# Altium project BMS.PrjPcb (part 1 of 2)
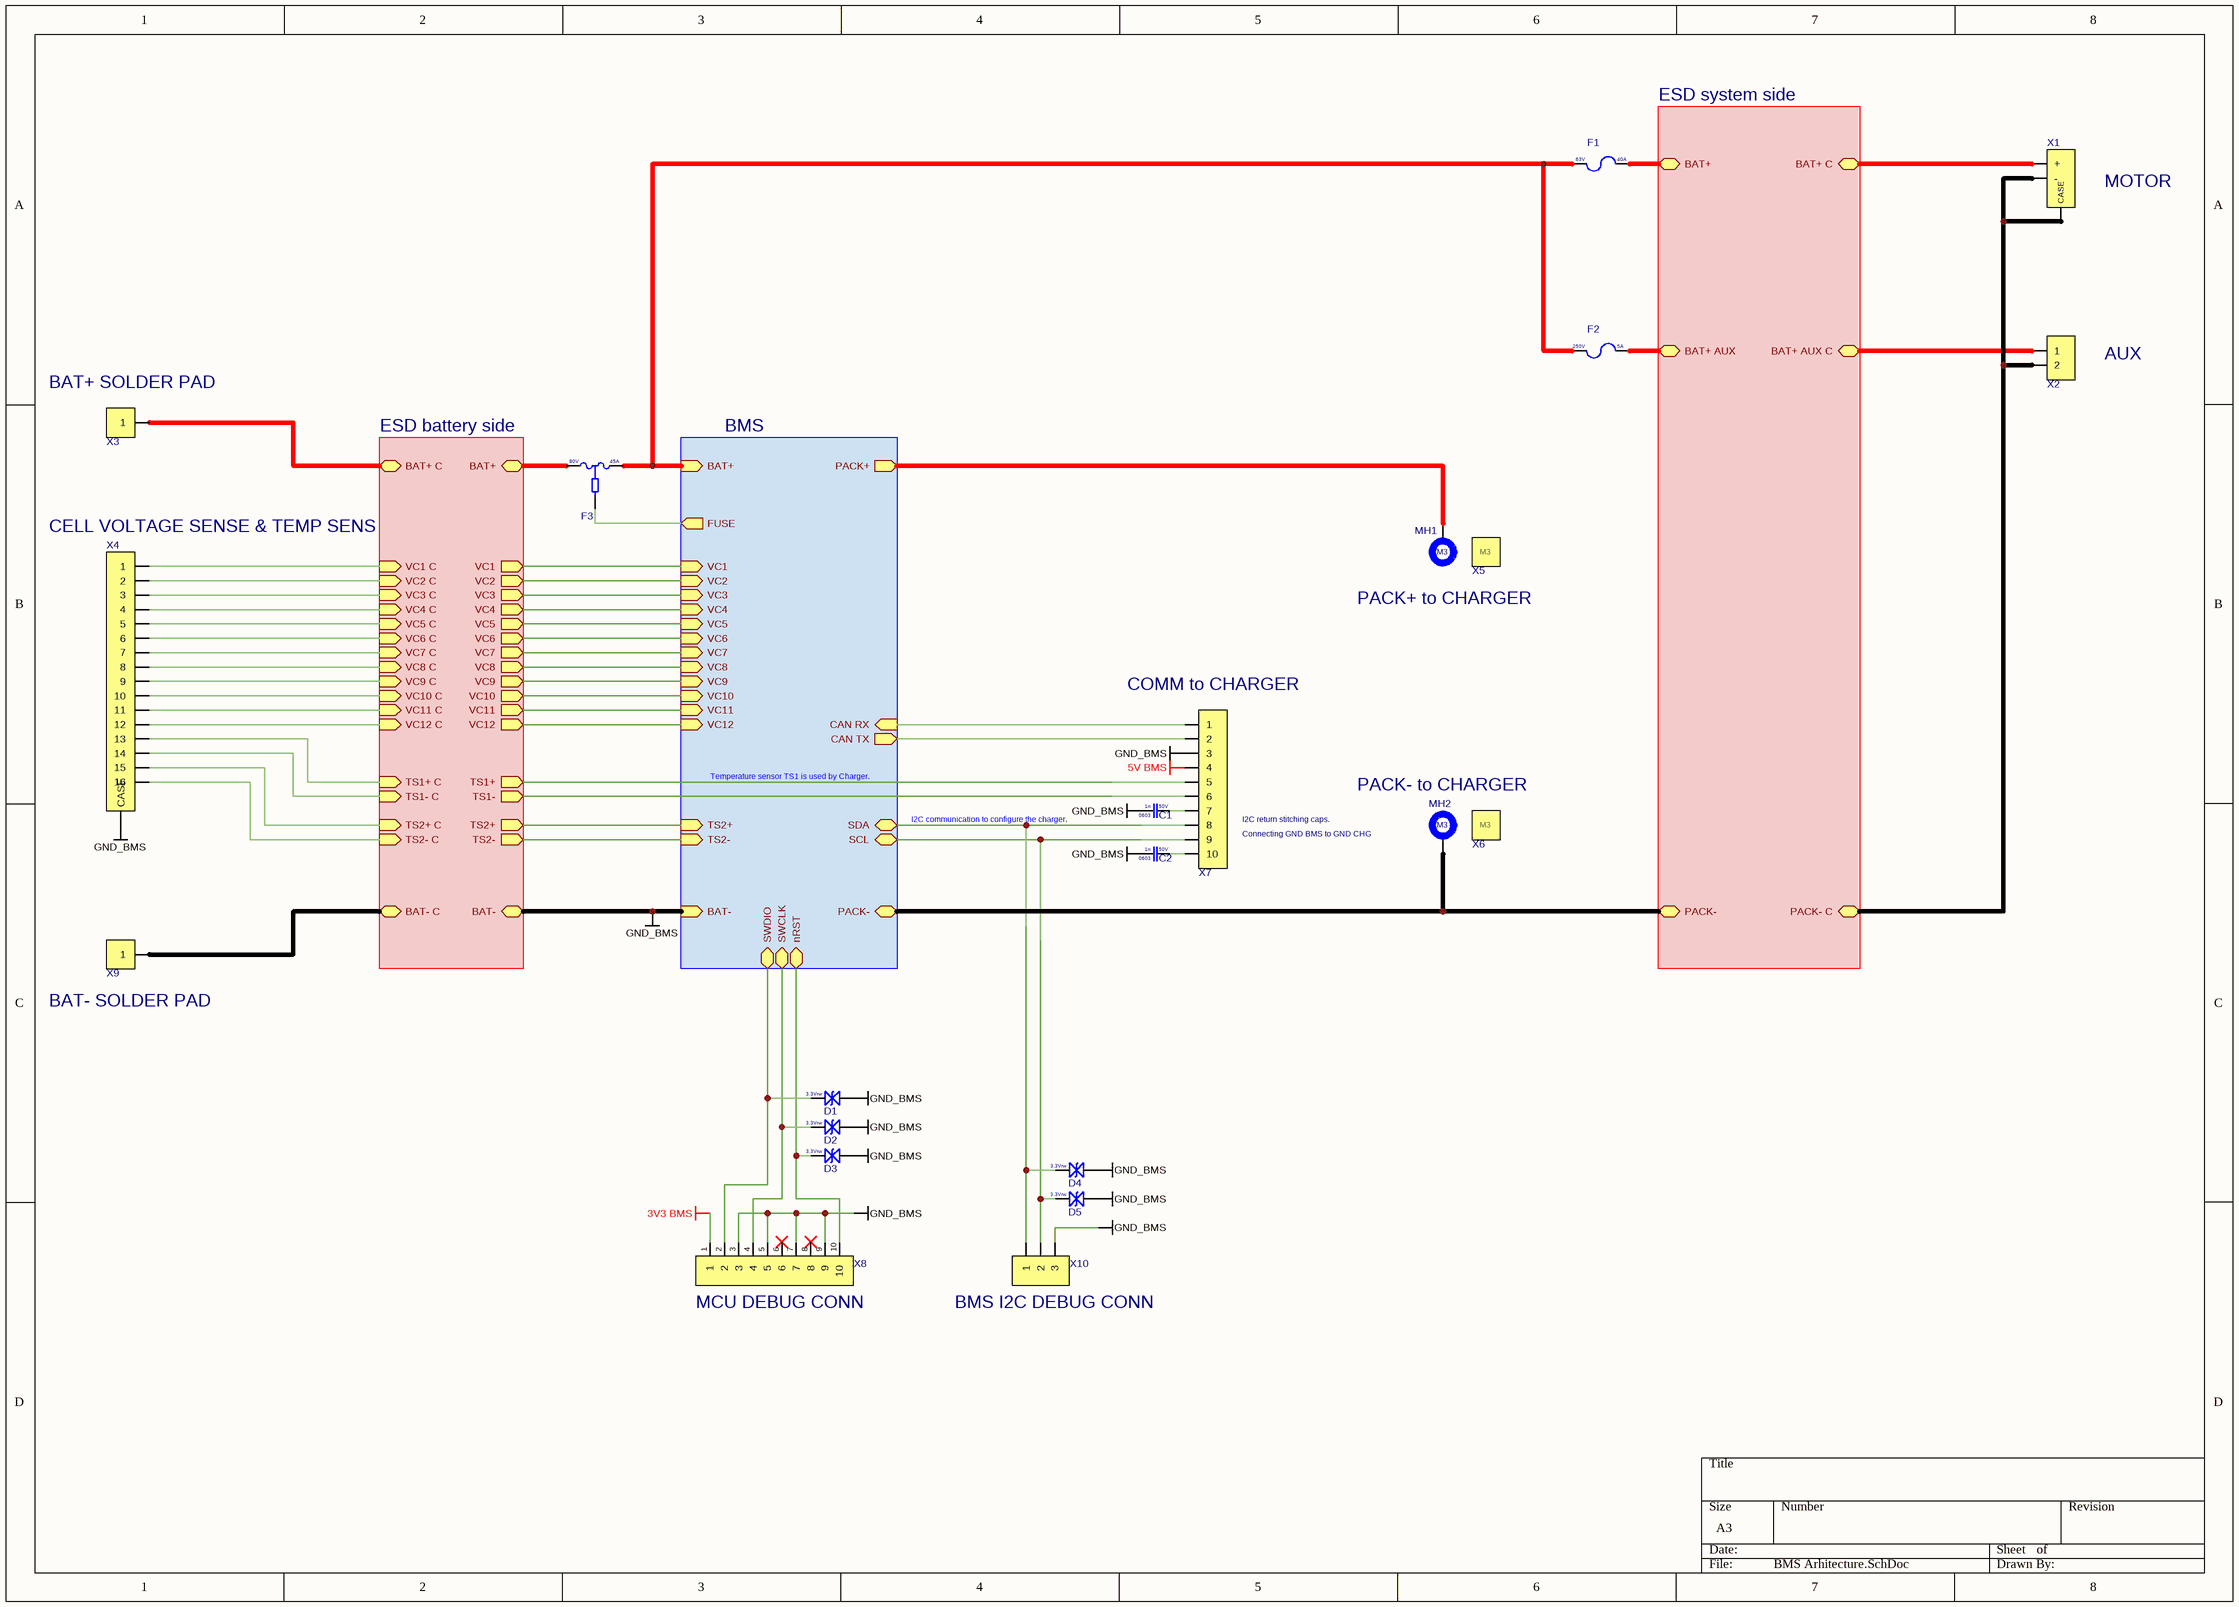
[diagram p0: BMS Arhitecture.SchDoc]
10 sheets, 241 parts. Net scope: hierarchical (ports join the sheet entries above them; power ports are global).
Board file: BMS PCB.PcbDoc
Sheets:
  BMS Arhitecture.SchDoc
    BMS = BMS.SchDoc
      BQ76952 BMS = BQ76952 BMS.SchDoc
      BQ34Z100 FUEL GAUGE = BQ34Z100 FUEL GAUGE.SchDoc
      MCU = MCU.SchDoc
      BAT+ to 5V1 STEP-DOWN = BAT+ to 5V1 STEP-DOWN.SchDoc
      5V to 3V3 LDO = 5V to 3V3 LDO.SchDoc
      BQ7721606 PROTECTOR = BQ7721606.SchDoc
    ESD system side = ESD system side.SchDoc
    ESD battery side = ESD battery side.SchDoc

## Sheet BMS Arhitecture.SchDoc
size A3; SheetNumber: 1; SheetTotal: 10

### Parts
C1  Voltage Rating: 50V  Case Code (Imperial): 0603  Capacitance: 1n  [CAP 0603]  (hidden comment: CL10B102KB8NNNC)
C2  Voltage Rating: 50V  Case Code (Imperial): 0603  Capacitance: 1n  [CAP 0603]  (hidden comment: CL10B102KB8NNNC)
D1  V_RWM: 3.3Vrw  [SOD-523]  (hidden comment: H3V3LD5B)
D2  V_RWM: 3.3Vrw  [SOD-523]  (hidden comment: H3V3LD5B)
D3  V_RWM: 3.3Vrw  [SOD-523]  (hidden comment: H3V3LD5B)
D4  V_RWM: 3.3Vrw  [SOD-523]  (hidden comment: H3V3LD5B)
D5  V_RWM: 3.3Vrw  [SOD-523]  (hidden comment: H3V3LD5B)
F1  Voltage: 63V  Hold Current: 40A  [JFC2410-1500TS]  (hidden comment: STS2400)
F2  Voltage: 250V  Hold Current: 5A  [JFC2410-1500TS]  (hidden comment: JFC2410-1500TS)
F3  Voltage: 80V  Hold Current: 45A  [WSFD4530]  (hidden comment: WSFD4530)
MH1  Hole size: M3  [M3 Plated]  (hidden comment: M?)  (no BOM)
MH2  Hole size: M3  [M3 Plated]  (hidden comment: M?)  (no BOM)
X1  XT30PW-F20.G.Y  [XT30PW-F20.G.Y]  (value not drawn)
X2  S2B-XH-A(LF)(SN)  [S2B-XH-A(LF)(SN)]  (value not drawn)
X3  Solder pad SMD 5x5mm  [Solder pad SMD 5x5mm]  (value not drawn)  (no BOM)
X4  FPC-1.0FX-16PWCR-H20  [FPC-1.0FX-16PWCR-H20]  (value not drawn)
X5  971060324  [971060324]  (value not drawn)
X6  971060324  [971060324]  (value not drawn)
X7  PM127-2-05-S-4.3  [Female header 2x5 1.27mm SMD Vertical]  (value not drawn)
X8  FTSH-105-01-L-D-RA-K  [JTAG Cortex connector THT Right-angle]  (value not drawn)
X9  Solder pad SMD 5x5mm  [Solder pad SMD 5x5mm]  (value not drawn)  (no BOM)
X10  PZ254R-11-03P  [Pin header 1x3 2.54mmP THT Right-angle]  (value not drawn)

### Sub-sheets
BMS = BMS.SchDoc: BAT+ (in), BAT- (in), VC1 (in), VC2 (in), VC3 (in), VC4 (in), VC5 (in), VC6 (in), VC7 (in), VC8 (in), VC9 (in), VC10 (in), VC11 (in), VC12 (in), PACK+ (out), PACK- (bidir), SCL (bidir), SDA (bidir), TS2+ (in), TS2- (in), SWDIO (bidir), SWCLK (bidir), nRST (bidir), FUSE (out), CAN TX (out), CAN RX (in)
ESD battery side = ESD battery side.schDoc: VC1 C (in), VC2 C (in), VC3 C (in), VC4 C (in), VC5 C (in), VC6 C (in), VC7 C (in), VC8 C (in), VC9 C (in), VC10 C (in), VC11 C (in), VC12 C (in), TS1+ C (in), TS1- C (in), TS2+ C (in), TS2- C (in), VC1 (out), VC2 (out), VC3 (out), VC4 (out), VC5 (out), VC6 (out), VC7 (out), VC8 (out), VC9 (out), VC10 (out), VC11 (out), VC12 (out), TS1+ (out), TS1- (out), TS2+ (out), TS2- (out), BAT+ C (bidir), BAT- C (bidir), BAT- (bidir), BAT+ (bidir)
ESD system side = ESD system side.SchDoc: BAT+ C (bidir), BAT+ (bidir), PACK- C (bidir), PACK- (bidir), BAT+ AUX (bidir), BAT+ AUX C (bidir)

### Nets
3V3 BMS: X8.1  [project net VDD]
5V BMS: X7.4
GND_BMS: C1.1 C2.1 D1.A D2.A D3.A D4.A D5.A X4.CASE X7.3 X8.3 X8.5 X8.7 X8.9 X9.1 X10.3 ; sheet BMS/BAT-, sheet ESD battery side/BAT- C, sheet ESD battery side/BAT-
PACK-: MH2.1 X1.- X1.CASE X2.2 ; sheet BMS/PACK-, sheet ESD system side/PACK- C, sheet ESD system side/PACK-
BAT+: F1.1 F2.1 F3.2 ; sheet BMS/BAT+
BAT+ C: F3.1 X3.1 ; sheet ESD battery side/BAT+ C, sheet ESD battery side/BAT+
C1: X4.1 ; sheet BMS/VC1, sheet ESD battery side/VC1 C, sheet ESD battery side/VC1
C2: X4.2 ; sheet BMS/VC2, sheet ESD battery side/VC2 C, sheet ESD battery side/VC2
C3: X4.3 ; sheet BMS/VC3, sheet ESD battery side/VC3 C, sheet ESD battery side/VC3
C4: X4.4 ; sheet BMS/VC4, sheet ESD battery side/VC4 C, sheet ESD battery side/VC4
C5: X4.5 ; sheet BMS/VC5, sheet ESD battery side/VC5 C, sheet ESD battery side/VC5
C6: X4.6 ; sheet BMS/VC6, sheet ESD battery side/VC6 C, sheet ESD battery side/VC6
C7: X4.7 ; sheet BMS/VC7, sheet ESD battery side/VC7 C, sheet ESD battery side/VC7
C8: X4.8 ; sheet BMS/VC8, sheet ESD battery side/VC8 C, sheet ESD battery side/VC8
C9: X4.9 ; sheet BMS/VC9, sheet ESD battery side/VC9 C, sheet ESD battery side/VC9
C10: X4.10 ; sheet BMS/VC10, sheet ESD battery side/VC10 C, sheet ESD battery side/VC10
C11: X4.11 ; sheet BMS/VC11, sheet ESD battery side/VC11 C, sheet ESD battery side/VC11
C12: X4.12 ; sheet BMS/VC12, sheet ESD battery side/VC12 C, sheet ESD battery side/VC12
CAN RX: X7.1 ; sheet BMS/CAN RX
CAN TX: X7.2 ; sheet BMS/CAN TX
nRST: D3.K X8.10 ; sheet BMS/nRST
PACK+: MH1.1 ; sheet BMS/PACK+
SCLt: D5.K X7.9 X10.2 ; sheet BMS/SCL
SDAt: D4.K X7.8 X10.1 ; sheet BMS/SDA
SWCLK: D2.K X8.4 ; sheet BMS/SWCLK
SWDIO: D1.K X8.2 ; sheet BMS/SWDIO
TS1: X4.15 ; sheet BMS/TS2+, sheet ESD battery side/TS2+ C, sheet ESD battery side/TS2+
TS1+ C: X4.13 X7.5 ; sheet ESD battery side/TS1+ C, sheet ESD battery side/TS1+
TS1- C: X4.14 X7.6 ; sheet ESD battery side/TS1- C, sheet ESD battery side/TS1-
TS2- C: X4.16 ; sheet BMS/TS2-, sheet ESD battery side/TS2- C, sheet ESD battery side/TS2-
NetC1_2: C1.2 X7.7
NetC2_2: C2.2 X7.10
NetC38_2: F1.2 X1.+ ; sheet ESD system side/BAT+ C, sheet ESD system side/BAT+
NetC39_2: F2.2 X2.1 ; sheet ESD system side/BAT+ AUX, sheet ESD system side/BAT+ AUX C
NetF3_3: F3.3 ; sheet BMS/FUSE

Not connected (* = marked no-connect by the designer): X8 6* 8*

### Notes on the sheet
- (near X1) MOTOR
- (near X3) BAT+ SOLDER PAD
- AUX
- (near X4) CELL VOLTAGE SENSE & TEMP SENS
- PACK+ to CHARGER
- (near X7) COMM to CHARGER
- Temperature sensor TS1 is used by Charger.
- I2C communication to configure the charger.
- (near X7) I2C return stitching caps.
- (near X7) Connecting GND BMS to GND CHG
- PACK- to CHARGER
- (near X9) BAT- SOLDER PAD
- (near X8) MCU DEBUG CONN
- (near X10) BMS I2C DEBUG CONN

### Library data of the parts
C1 C2 = CL10B102KB8NNNC: Cap 1nF 50V 0603 X7R; Manufacturer: Samsung
D1-D5 = H3V3LD5B: ESD TVS 3.3Vrw 0.2uA 12.5pF; Manufacturer: hongjiacheng
F1 = STS2400: Fuse SMD 63V 40A 2410; Manufacturer: Reomax
F2 = JFC2410-1500TS: Fuse SMD 250V 5A 2410; Manufacturer: JDT Fuse
F3 = WSFD4530: Fuse Trip SMD 80V 45A 120Abr; Manufacturer: TLC Electronic
MH1 MH2 = Mounting hole: Generic mounting hole symbol
X1 = XT30PW-F20.G.Y: XT30 Female THT Right-angle; Manufacturer: Changzhou Amass Elec
X2 = S2B-XH-A(LF)(SN): JST XH 1x2 2.50mmP THT Right-angle
X4 = FPC-1.0FX-16PWCR-H20: FPC connector 16p 1.0mmP SMD Right-angle; Manufacturer: XUNPU
X5 X6 = 971060324: Standoff M3x6x6 Mechanical Male-Female; Manufacturer: Wurth Elektronik
X7 = PM127-2-05-S-4.3: Female header 2x5 1.27mmP SMD Vertical; Manufacturer: HCTL
X8 = FTSH-105-01-L-D-RA-K: JTAG Cortex MCU Debug connector 2x5P 1.27mmP THT Right-angle; Manufacturer: Samtec
X10 = PZ254R-11-03P: Pin header 1x3 2.54mmP THT Right-angle; Manufacturer: XFCN

## Sheet BMS.SchDoc
size A3; SheetNumber: 2; SheetTotal: 10
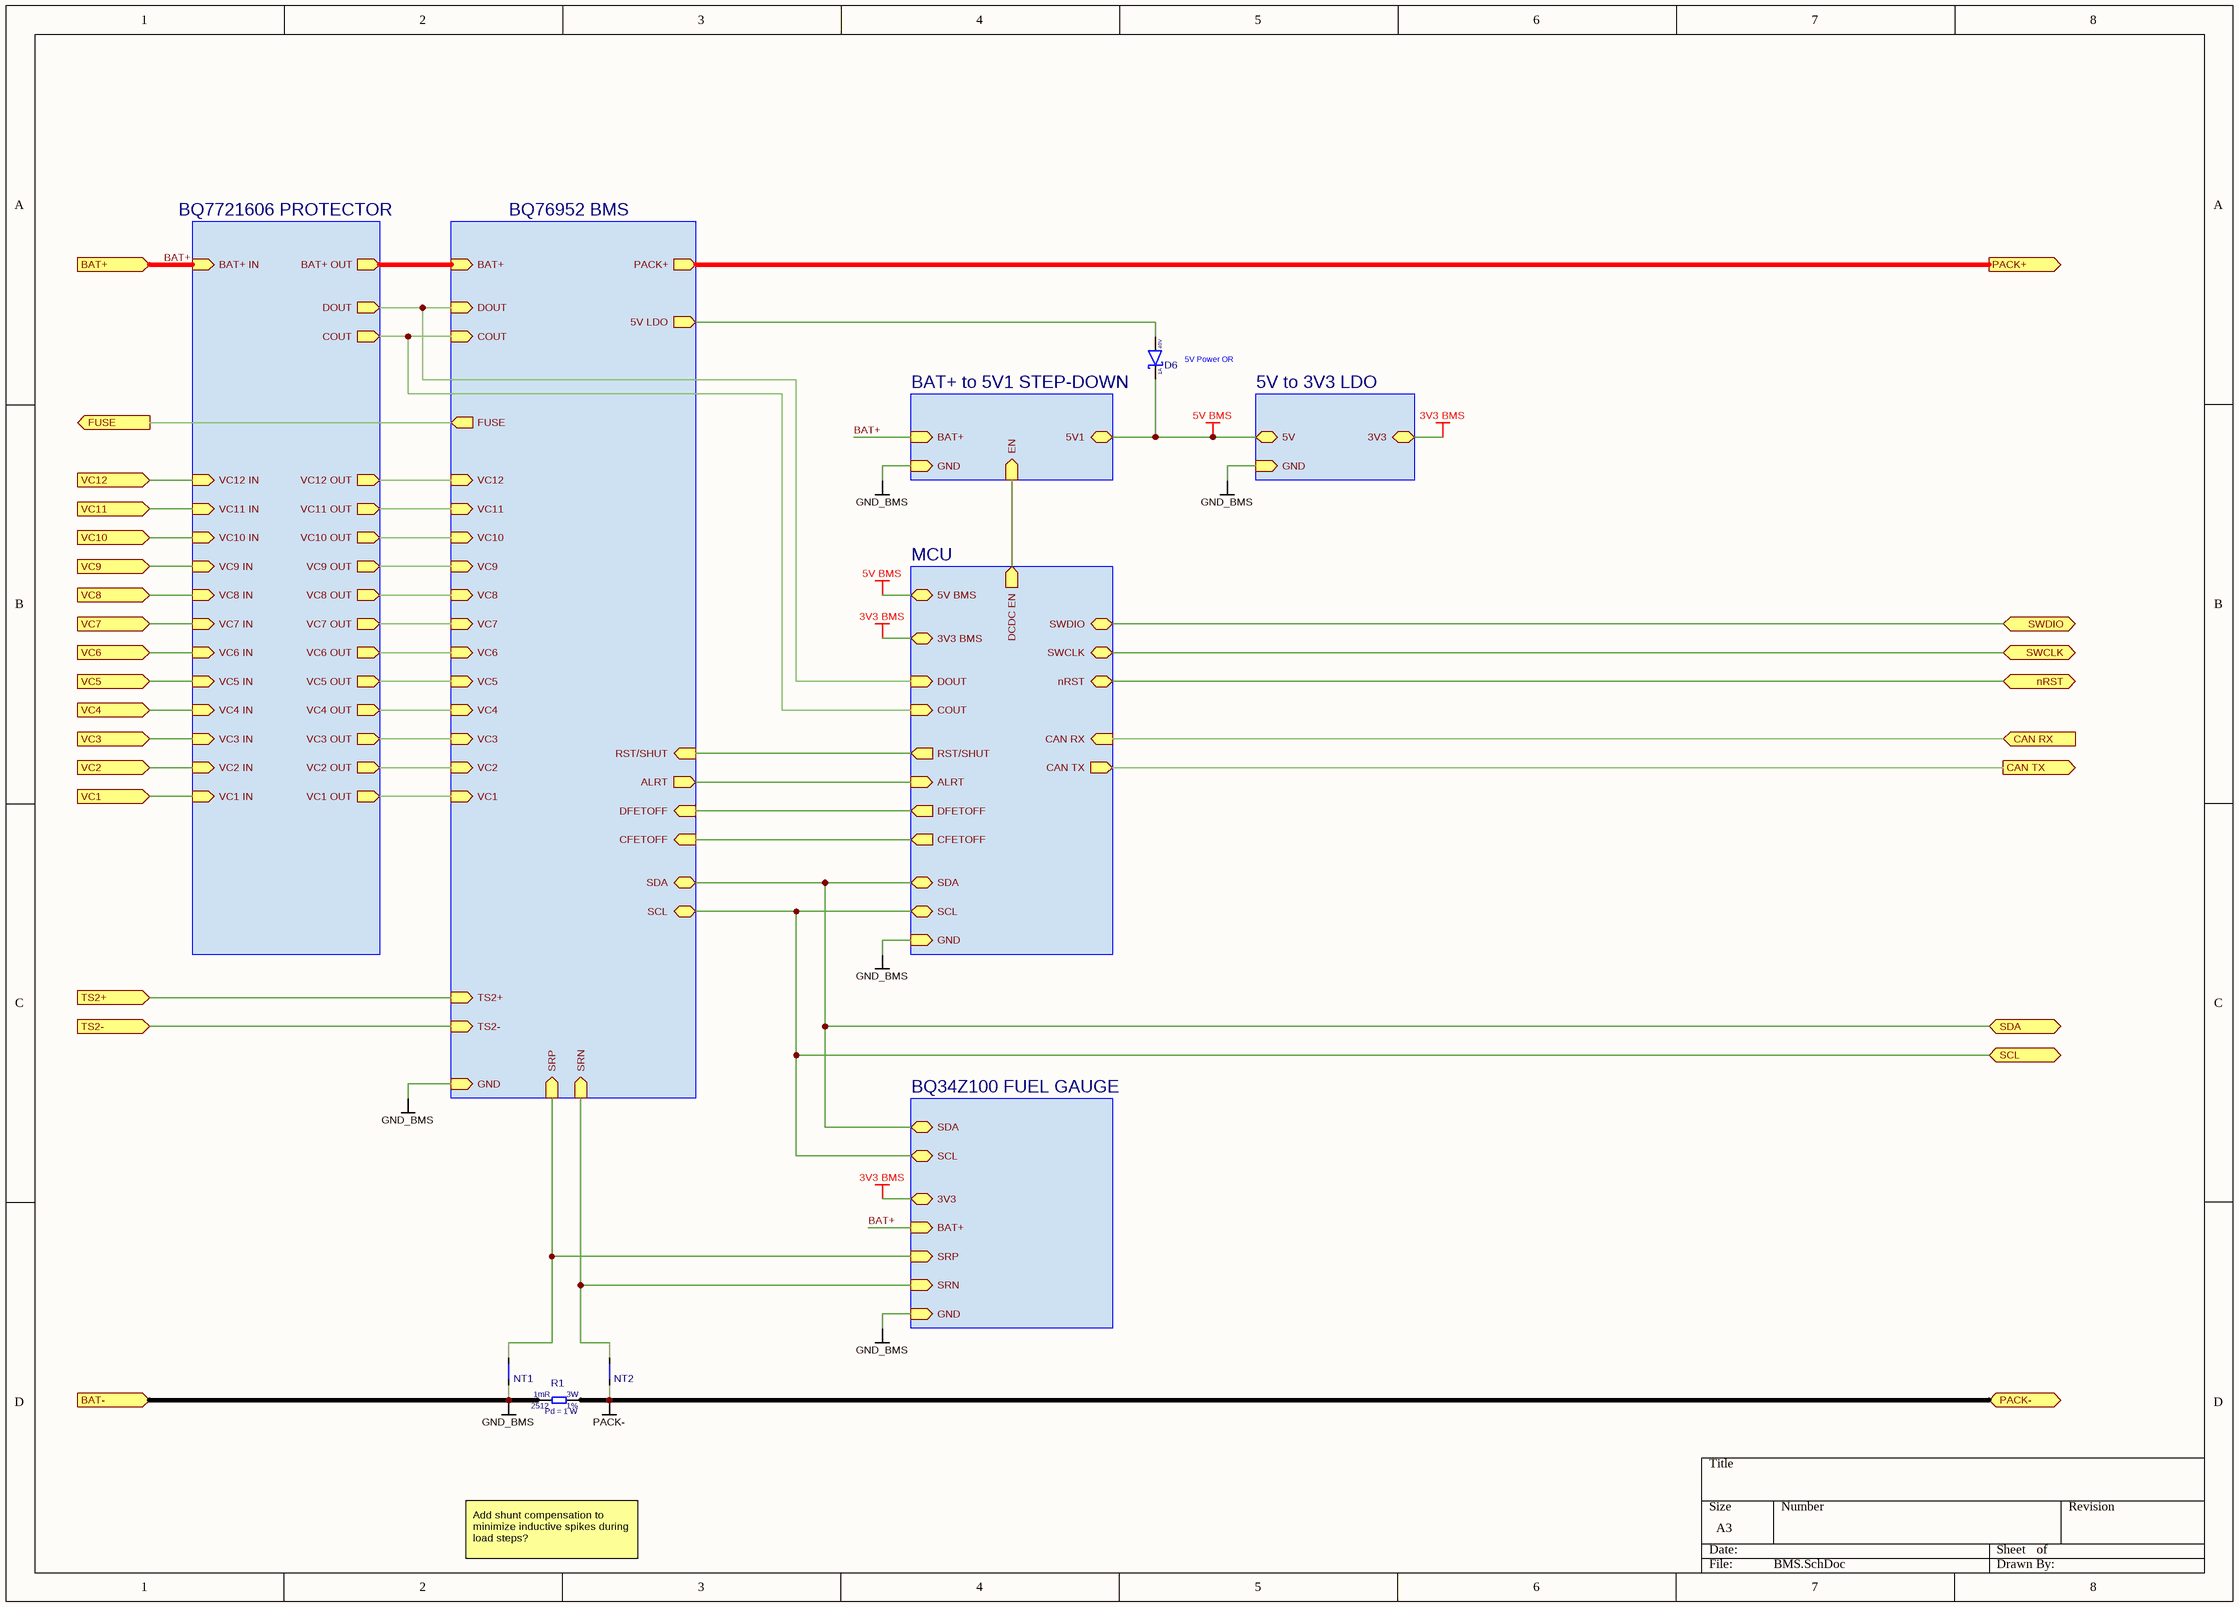
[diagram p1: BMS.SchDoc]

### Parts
D6  Forward Current: 1A  Reverse Voltage: 40V  [SOD-323]  (hidden comment: 1N5819WS)
NT1  NT  [NETTIE_0.3MM]  (value not drawn)  (net tie, no BOM)
NT2  NT  [NETTIE_0.3MM]  (value not drawn)  (net tie, no BOM)
R1  Pd = 1 W  Resistance Tolerance: 1%  Resistance: 1mR  Power Rating: 3W  Case Code (Imperial): 2512  [2512 Shunt]

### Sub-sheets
5V to 3V3 LDO = 5V to 3V3 LDO.SchDoc: 5V (bidir), 3V3 (bidir), GND (in)
BAT+ to 5V1 STEP-DOWN = BAT+ to 5V1 STEP-DOWN.SchDoc: 5V1 (bidir), BAT+ (in), EN (in), GND (in)
BQ34Z100 FUEL GAUGE = BQ34Z100 FUEL GAUGE.SchDoc: SRP (in), SRN (in), SDA (bidir), SCL (bidir), BAT+ (in), GND (in), 3V3 (bidir)
BQ76952 BMS = BQ76952 BMS.SchDoc: VC12 (in), VC11 (in), VC10 (in), VC9 (in), VC8 (in), VC7 (in), VC6 (in), VC5 (in), VC4 (in), VC3 (in), VC2 (in), VC1 (in), TS2+ (in), TS2- (in), BAT+ (in), PACK+ (out), 5V LDO (out), SRP (in), SRN (in), SDA (bidir), SCL (bidir), ALRT (out), DFETOFF (in), CFETOFF (in), RST/SHUT (in), GND (in), DOUT (in), COUT (in), FUSE (out)
BQ7721606 PROTECTOR = BQ7721606.schDoc: VC12 IN (in), VC11 IN (in), VC10 IN (in), VC9 IN (in), VC8 IN (in), VC7 IN (in), VC6 IN (in), VC5 IN (in), VC4 IN (in), VC3 IN (in), VC2 IN (in), VC1 IN (in), VC12 OUT (out), VC11 OUT (out), VC10 OUT (out), VC9 OUT (out), VC8 OUT (out), VC7 OUT (out), VC6 OUT (out), VC5 OUT (out), VC4 OUT (out), VC3 OUT (out), VC2 OUT (out), VC1 OUT (out), BAT+ IN (in), BAT+ OUT (out), DOUT (out), COUT (out)
MCU = MCU.SchDoc: DCDC EN (out), 5V BMS (bidir), 3V3 BMS (bidir), SDA (bidir), SCL (bidir), ALRT (in), DFETOFF (out), CFETOFF (out), RST/SHUT (out), GND (in), nRST (bidir), SWCLK (bidir), SWDIO (bidir), DOUT (in), COUT (in), CAN RX (in), CAN TX (out)

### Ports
BAT+ (in, see BMS Arhitecture[3B], BAT+ to 5V1 STEP-DOWN[3B], BQ34Z100 FUEL GAUGE[3A], BQ76952 BMS[1A]), BAT- (in, see BMS Arhitecture[3C], ESD battery side[5C]), CAN RX (in, see BMS Arhitecture[4B], MCU[8B]), CAN TX (out, see BMS Arhitecture[4B], MCU[8B]), FUSE (out, see BMS Arhitecture[3B], BQ76952 BMS[3B]), nRST (bidir, see BMS Arhitecture[3C], MCU[8C]), PACK+ (out, see BMS Arhitecture[4B], BQ76952 BMS[8A]), PACK- (bidir, see BMS Arhitecture[4C], ESD system side[3C]), SCL (bidir, see BMS Arhitecture[4C], BQ34Z100 FUEL GAUGE[5B], BQ76952 BMS[7C], MCU[1B]), SDA (bidir, see BMS Arhitecture[4C], BQ34Z100 FUEL GAUGE[5B], BQ76952 BMS[7C], MCU[1B]), SWCLK (bidir, see BMS Arhitecture[3C], MCU[8C]), SWDIO (bidir, see BMS Arhitecture[3C], MCU[8C]), TS2+ (in, see BMS Arhitecture[3C], BQ76952 BMS[3C], ESD battery side[5C]), TS2- (in, see BMS Arhitecture[3C], BQ76952 BMS[3C], ESD battery side[5C]), VC1 (in, see BMS Arhitecture[3B], BQ76952 BMS[1C], ESD battery side[5B]), VC2 (in, see BMS Arhitecture[3B], BQ76952 BMS[1C], ESD battery side[5B]), VC3 (in, see BMS Arhitecture[3B], BQ76952 BMS[1C], ESD battery side[5B]), VC4 (in, see BMS Arhitecture[3B], BQ76952 BMS[1C], ESD battery side[5B]), VC5 (in, see BMS Arhitecture[3B], BQ76952 BMS[1C], ESD battery side[5B]), VC6 (in, see BMS Arhitecture[3B], BQ76952 BMS[1C], ESD battery side[5B]), VC7 (in, see BMS Arhitecture[3B], BQ76952 BMS[1C], ESD battery side[5B]), VC8 (in, see BMS Arhitecture[3B], BQ76952 BMS[1B], ESD battery side[5B]), VC9 (in, see BMS Arhitecture[3B], BQ76952 BMS[1B], ESD battery side[5B]), VC10 (in, see BMS Arhitecture[3B], BQ76952 BMS[1B], ESD battery side[5B]), VC11 (in, see BMS Arhitecture[3B], BQ76952 BMS[1B], ESD battery side[5B]), VC12 (in, see BMS Arhitecture[3B], BQ76952 BMS[1B], ESD battery side[5B])

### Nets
3V3 BMS: sheet BQ34Z100 FUEL GAUGE/3V3, sheet MCU/3V3 BMS, sheet 5V to 3V3 LDO/3V3  [project net VDD]
5V BMS: D6.K ; sheet MCU/5V BMS, sheet BAT+ to 5V1 STEP-DOWN/5V1, sheet 5V to 3V3 LDO/5V
GND_BMS: NT1.1 R1.1 ; port BAT-, sheet BQ76952 BMS/GND, sheet BQ34Z100 FUEL GAUGE/GND, sheet MCU/GND, sheet BAT+ to 5V1 STEP-DOWN/GND, sheet 5V to 3V3 LDO/GND
PACK-: NT2.1 R1.2 ; port PACK-
ALRT: sheet BQ76952 BMS/ALRT, sheet MCU/ALRT
BAT+: port BAT+, sheet BQ76952 BMS/BAT+, sheet BQ34Z100 FUEL GAUGE/BAT+, sheet BAT+ to 5V1 STEP-DOWN/BAT+, sheet BQ7721606 PROTECTOR/BAT+ IN, sheet BQ7721606 PROTECTOR/BAT+ OUT
C1: port VC1, sheet BQ76952 BMS/VC1, sheet BQ7721606 PROTECTOR/VC1 IN, sheet BQ7721606 PROTECTOR/VC1 OUT
C2: port VC2, sheet BQ76952 BMS/VC2, sheet BQ7721606 PROTECTOR/VC2 IN, sheet BQ7721606 PROTECTOR/VC2 OUT
C3: port VC3, sheet BQ76952 BMS/VC3, sheet BQ7721606 PROTECTOR/VC3 IN, sheet BQ7721606 PROTECTOR/VC3 OUT
C4: port VC4, sheet BQ76952 BMS/VC4, sheet BQ7721606 PROTECTOR/VC4 IN, sheet BQ7721606 PROTECTOR/VC4 OUT
C5: port VC5, sheet BQ76952 BMS/VC5, sheet BQ7721606 PROTECTOR/VC5 IN, sheet BQ7721606 PROTECTOR/VC5 OUT
C6: port VC6, sheet BQ76952 BMS/VC6, sheet BQ7721606 PROTECTOR/VC6 IN, sheet BQ7721606 PROTECTOR/VC6 OUT
C7: port VC7, sheet BQ76952 BMS/VC7, sheet BQ7721606 PROTECTOR/VC7 IN, sheet BQ7721606 PROTECTOR/VC7 OUT
C8: port VC8, sheet BQ76952 BMS/VC8, sheet BQ7721606 PROTECTOR/VC8 IN, sheet BQ7721606 PROTECTOR/VC8 OUT
C9: port VC9, sheet BQ76952 BMS/VC9, sheet BQ7721606 PROTECTOR/VC9 IN, sheet BQ7721606 PROTECTOR/VC9 OUT
C10: port VC10, sheet BQ76952 BMS/VC10, sheet BQ7721606 PROTECTOR/VC10 IN, sheet BQ7721606 PROTECTOR/VC10 OUT
C11: port VC11, sheet BQ76952 BMS/VC11, sheet BQ7721606 PROTECTOR/VC11 IN, sheet BQ7721606 PROTECTOR/VC11 OUT
C12: port VC12, sheet BQ76952 BMS/VC12, sheet BQ7721606 PROTECTOR/VC12 IN, sheet BQ7721606 PROTECTOR/VC12 OUT
CAN RX: port CAN RX, sheet MCU/CAN RX
CAN TX: port CAN TX, sheet MCU/CAN TX
CFETOFF: sheet BQ76952 BMS/CFETOFF, sheet MCU/CFETOFF
COUT: sheet BQ76952 BMS/COUT, sheet MCU/COUT, sheet BQ7721606 PROTECTOR/COUT
DCDC EN: sheet MCU/DCDC EN, sheet BAT+ to 5V1 STEP-DOWN/EN
DFETOFF: sheet BQ76952 BMS/DFETOFF, sheet MCU/DFETOFF
DOUT: sheet BQ76952 BMS/DOUT, sheet MCU/DOUT, sheet BQ7721606 PROTECTOR/DOUT
nRST: port nRST, sheet MCU/nRST
PACK+: port PACK+, sheet BQ76952 BMS/PACK+
REG1: D6.A ; sheet BQ76952 BMS/5V LDO
RST/SHUT: sheet BQ76952 BMS/RST/SHUT, sheet MCU/RST/SHUT
SCLt: port SCL, sheet BQ76952 BMS/SCL, sheet BQ34Z100 FUEL GAUGE/SCL, sheet MCU/SCL
SDAt: port SDA, sheet BQ76952 BMS/SDA, sheet BQ34Z100 FUEL GAUGE/SDA, sheet MCU/SDA
SWCLK: port SWCLK, sheet MCU/SWCLK
SWDIO: port SWDIO, sheet MCU/SWDIO
TS1: port TS2+, sheet BQ76952 BMS/TS2+
TS2- C: port TS2-, sheet BQ76952 BMS/TS2-
NetF3_3: port FUSE, sheet BQ76952 BMS/FUSE
NetNT1_2: NT1.2 ; sheet BQ76952 BMS/SRP, sheet BQ34Z100 FUEL GAUGE/SRP
NetNT2_2: NT2.2 ; sheet BQ76952 BMS/SRN, sheet BQ34Z100 FUEL GAUGE/SRN

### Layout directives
net class BAT+: (no net found under the mark)

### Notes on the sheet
- (near D6) 5V Power OR
- Add shunt compensation to minimize inductive spikes during load steps?

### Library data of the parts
D6 = 1N5819WS: Schottky 40V 1A 600mVf SOD-323; Manufacturer: Guangdong Hottech
NT1 NT2 = NetTie: Net Tie
R1 = HoYLR2512E-3W-1mR-1%: RES 1mR 2512 3W 1%; Manufacturer: Miliohm

## Sheet BQ76952 BMS.SchDoc
size A3; SheetNumber: 3; SheetTotal: 10
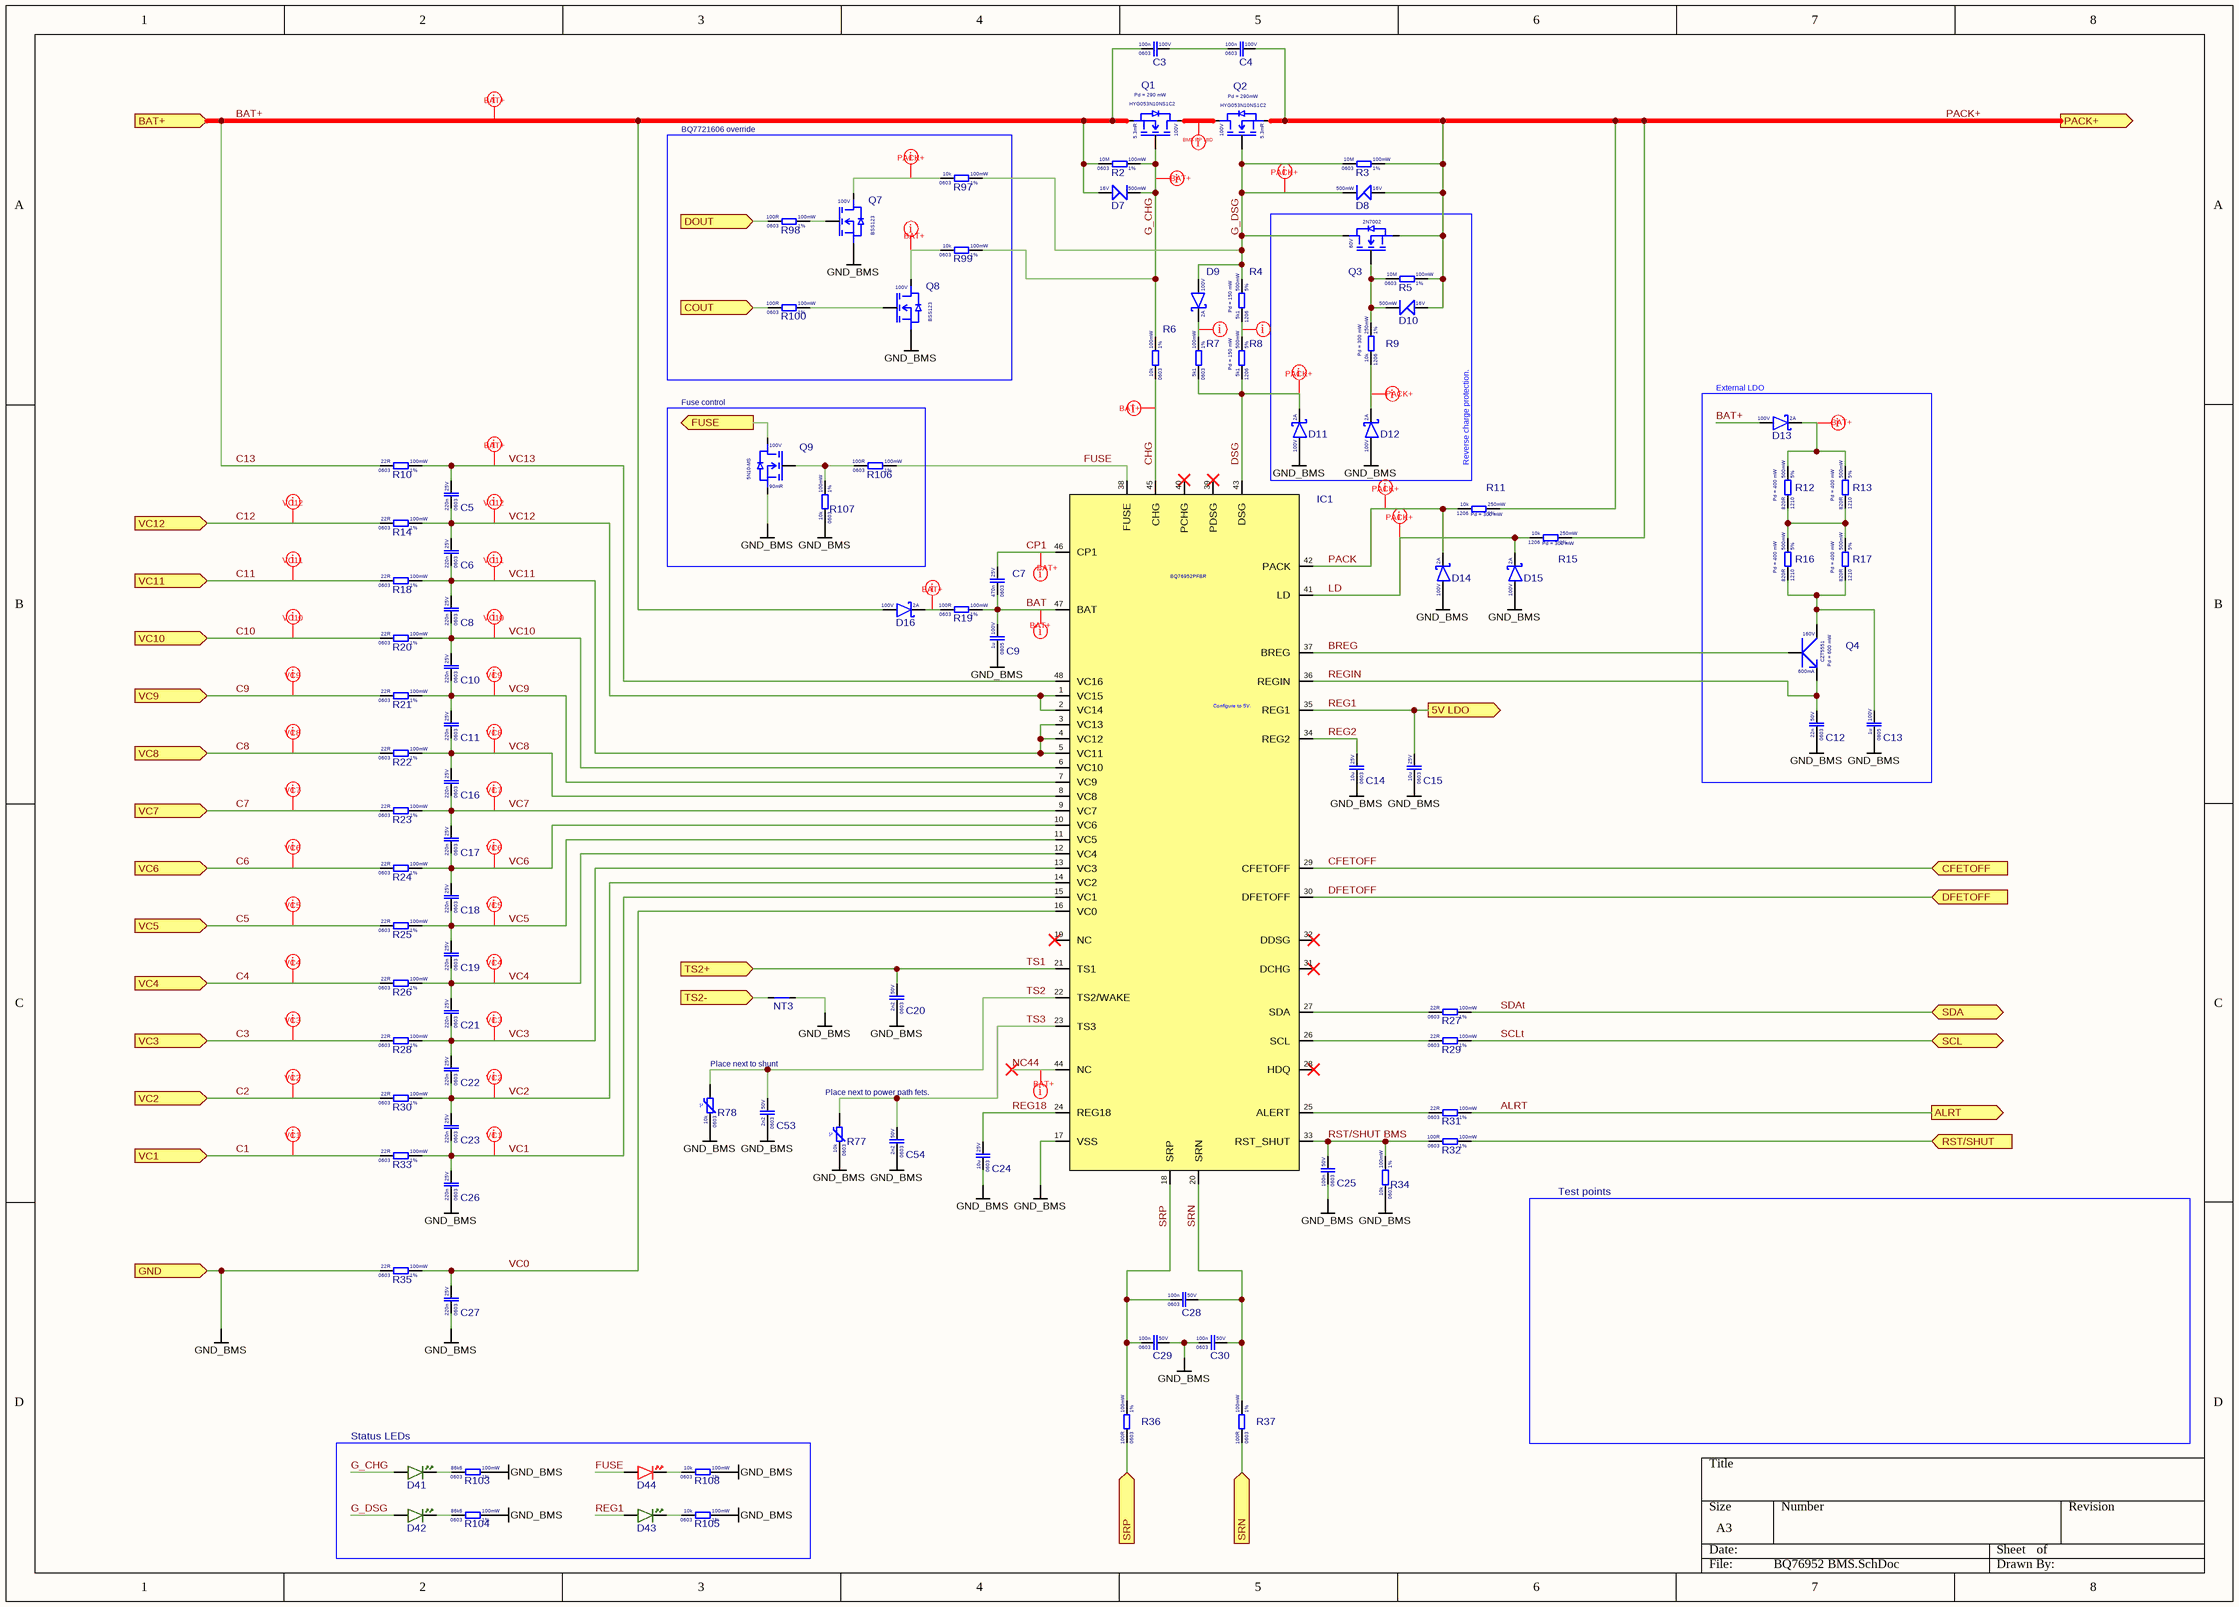
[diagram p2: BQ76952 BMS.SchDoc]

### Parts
C3  Voltage Rating: 100V  Case Code (Imperial): 0603  Capacitance: 100n  [CAP 0603]  (hidden comment: CC0603KRX7R0BB104)
C4  Voltage Rating: 100V  Case Code (Imperial): 0603  Capacitance: 100n  [CAP 0603]  (hidden comment: CC0603KRX7R0BB104)
C5  Voltage Rating: 25V  Case Code (Imperial): 0603  Capacitance: 220n  [CAP 0603]  (hidden comment: CL10B224KA8NNNC)
C6  Voltage Rating: 25V  Case Code (Imperial): 0603  Capacitance: 220n  [CAP 0603]  (hidden comment: CL10B224KA8NNNC)
C7  Voltage Rating: 25V  Case Code (Imperial): 0603  Capacitance: 470n  [CAP 0603]  (hidden comment: CL10B474KA8NNNC)
C8  Voltage Rating: 25V  Case Code (Imperial): 0603  Capacitance: 220n  [CAP 0603]  (hidden comment: CL10B224KA8NNNC)
C9  Voltage Rating: 100V  Case Code (Imperial): 0805  Capacitance: 1u  [Cap_0805]  (hidden comment: CC0805KKX7R0BB105)
C10  Voltage Rating: 25V  Case Code (Imperial): 0603  Capacitance: 220n  [CAP 0603]  (hidden comment: CL10B224KA8NNNC)
C11  Voltage Rating: 25V  Case Code (Imperial): 0603  Capacitance: 220n  [CAP 0603]  (hidden comment: CL10B224KA8NNNC)
C12  Voltage Rating: 50V  Case Code (Imperial): 0603  Capacitance: 22n  [CAP 0603]  (hidden comment: CL10B223KB8NNNC)
C13  Voltage Rating: 100V  Case Code (Imperial): 0805  Capacitance: 1u  [Cap_0805]  (hidden comment: CC0805KKX7R0BB105)
C14  Voltage Rating: 25V  Case Code (Imperial): 0603  Capacitance: 10u  [CAP 0603]  (hidden comment: CL10A106MA8NRNC)
C15  Voltage Rating: 25V  Case Code (Imperial): 0603  Capacitance: 10u  [CAP 0603]  (hidden comment: CL10A106MA8NRNC)
C16  Voltage Rating: 25V  Case Code (Imperial): 0603  Capacitance: 220n  [CAP 0603]  (hidden comment: CL10B224KA8NNNC)
C17  Voltage Rating: 25V  Case Code (Imperial): 0603  Capacitance: 220n  [CAP 0603]  (hidden comment: CL10B224KA8NNNC)
C18  Voltage Rating: 25V  Case Code (Imperial): 0603  Capacitance: 220n  [CAP 0603]  (hidden comment: CL10B224KA8NNNC)
C19  Voltage Rating: 25V  Case Code (Imperial): 0603  Capacitance: 220n  [CAP 0603]  (hidden comment: CL10B224KA8NNNC)
C20  Voltage Rating: 50V  Case Code (Imperial): 0603  Capacitance: 2n2  [CAP 0603]  (hidden comment: 0603B222K500NT)
C21  Voltage Rating: 25V  Case Code (Imperial): 0603  Capacitance: 220n  [CAP 0603]  (hidden comment: CL10B224KA8NNNC)
C22  Voltage Rating: 25V  Case Code (Imperial): 0603  Capacitance: 220n  [CAP 0603]  (hidden comment: CL10B224KA8NNNC)
C23  Voltage Rating: 25V  Case Code (Imperial): 0603  Capacitance: 220n  [CAP 0603]  (hidden comment: CL10B224KA8NNNC)
C24  Voltage Rating: 25V  Case Code (Imperial): 0603  Capacitance: 10u  [CAP 0603]  (hidden comment: CL10A106MA8NRNC)
C25  Voltage Rating: 50V  Case Code (Imperial): 0603  Capacitance: 100n  [CAP 0603]  (hidden comment: CC0603KRX7R9BB104)
C26  Voltage Rating: 25V  Case Code (Imperial): 0603  Capacitance: 220n  [CAP 0603]  (hidden comment: CL10B224KA8NNNC)
C27  Voltage Rating: 25V  Case Code (Imperial): 0603  Capacitance: 220n  [CAP 0603]  (hidden comment: CL10B224KA8NNNC)
C28  Voltage Rating: 50V  Case Code (Imperial): 0603  Capacitance: 100n  [CAP 0603]  (hidden comment: CC0603KRX7R9BB104)
C29  Voltage Rating: 50V  Case Code (Imperial): 0603  Capacitance: 100n  [CAP 0603]  (hidden comment: CC0603KRX7R9BB104)
C30  Voltage Rating: 50V  Case Code (Imperial): 0603  Capacitance: 100n  [CAP 0603]  (hidden comment: CC0603KRX7R9BB104)
C53  Voltage Rating: 50V  Case Code (Imperial): 0603  Capacitance: 2n2  [CAP 0603]  (hidden comment: 0603B222K500NT)
C54  Voltage Rating: 50V  Case Code (Imperial): 0603  Capacitance: 2n2  [CAP 0603]  (hidden comment: 0603B222K500NT)
D7  Power Rating: 500mW  Reverse Voltage: 16V  [SOD-123]  (hidden comment: BZT52C16)
D8  Power Rating: 500mW  Reverse Voltage: 16V  [SOD-123]  (hidden comment: BZT52C16)
D9  Forward Current: 2A  Reverse Voltage: 100V  [SMAF]  (hidden comment: SS210F)
D10  Power Rating: 500mW  Reverse Voltage: 16V  [SOD-123]  (hidden comment: BZT52C16)
D11  Forward Current: 2A  Reverse Voltage: 100V  [SMAF]  (hidden comment: SS210F)
D12  Forward Current: 2A  Reverse Voltage: 100V  [SMAF]  (hidden comment: SS210F)
D13  Forward Current: 2A  Reverse Voltage: 100V  [SMAF]  (hidden comment: SS210F)
D14  Forward Current: 2A  Reverse Voltage: 100V  [SMAF]  (hidden comment: SS210F)
D15  Forward Current: 2A  Reverse Voltage: 100V  [SMAF]  (hidden comment: SS210F)
D16  Forward Current: 2A  Reverse Voltage: 100V  [SMAF]  (hidden comment: SS210F)
D41  PSC-1608U52GC-G4  [DIODE_0603_GREEN]  (value not drawn)
D42  PSC-1608U52GC-G4  [DIODE_0603_GREEN]  (value not drawn)
D43  PSC-1608U52GC-G4  [DIODE_0603_GREEN]  (value not drawn)
D44  XL-1608SURC-06  [DIODE_0603_RED]  (value not drawn)
IC1  BQ76952PFBR  [TQFP-48 PFB]
NT3  NT  [NETTIE_0.3MM]  (value not drawn)  (net tie, no BOM)
Q1  Pd = 290 mW  Rds: 5.3mR  Voltage: 100V  [PDFN5*6-8L]
Q2  Pd = 290mW  Rds: 5.3mR  Voltage: 100V  [PDFN5*6-8L]
Q3  Voltage: 60V  [SOT-23 GSD]  (hidden comment: 2N7002)
Q4  Pd = 600 mW  Current: 600mA  Voltage: 160V  [SOT-223 NPN]
Q7  Voltage: 100V  [SOT-23 GSD]  (hidden comment: BSS123)
Q8  Voltage: 100V  [SOT-23 GSD]  (hidden comment: BSS123)
Q9  Rds: 90mR  Voltage: 100V  [SOT-23 GSD]  (hidden comment: 5N10-MS)
R2  Resistance Tolerance: 1%  Resistance: 10M  Power Rating: 100mW  Case Code (Imperial): 0603  [RES_0603]  (hidden comment: 0603WAF1005T5E)
R3  Resistance Tolerance: 1%  Resistance: 10M  Power Rating: 100mW  Case Code (Imperial): 0603  [RES_0603]  (hidden comment: 0603WAF1005T5E)
R4  Pd = 150 mW  Resistance Tolerance: 5%  Resistance: 5k1  Power Rating: 500mW  Case Code (Imperial): 1206  [RES_1206]
R5  Resistance Tolerance: 1%  Resistance: 10M  Power Rating: 100mW  Case Code (Imperial): 0603  [RES_0603]  (hidden comment: 0603WAF1005T5E)
R6  Resistance Tolerance: 1%  Resistance: 10k  Power Rating: 100mW  Case Code (Imperial): 0603  [RES_0603]  (hidden comment: 0603WAF1002T5E)
R7  Resistance Tolerance: 1%  Resistance: 5k1  Power Rating: 100mW  Case Code (Imperial): 0603  [RES_0603]  (hidden comment: 0603WAF5101T5E)
R8  Pd = 150 mW  Resistance Tolerance: 5%  Resistance: 5k1  Power Rating: 500mW  Case Code (Imperial): 1206  [RES_1206]
R9  Pd = 300 mW  Resistance Tolerance: 1%  Resistance: 10k  Power Rating: 250mW  Case Code (Imperial): 1206  [RES_1206]
R10  Resistance Tolerance: 1%  Resistance: 22R  Power Rating: 100mW  Case Code (Imperial): 0603  [RES_0603]  (hidden comment: 0603WAF220JT5E)
R11  Pd = 300 mW  Resistance Tolerance: 1%  Resistance: 10k  Power Rating: 250mW  Case Code (Imperial): 1206  [RES_1206]
R12  Pd = 400 mW  Resistance Tolerance: 5%  Resistance: 820R  Power Rating: 500mW  Case Code (Imperial): 1210  [RES_1210]
R13  Pd = 400 mW  Resistance Tolerance: 5%  Resistance: 820R  Power Rating: 500mW  Case Code (Imperial): 1210  [RES_1210]
R14  Resistance Tolerance: 1%  Resistance: 22R  Power Rating: 100mW  Case Code (Imperial): 0603  [RES_0603]  (hidden comment: 0603WAF220JT5E)
R15  Pd = 300 mW  Resistance Tolerance: 1%  Resistance: 10k  Power Rating: 250mW  Case Code (Imperial): 1206  [RES_1206]
R16  Pd = 400 mW  Resistance Tolerance: 5%  Resistance: 820R  Power Rating: 500mW  Case Code (Imperial): 1210  [RES_1210]
R17  Pd = 400 mW  Resistance Tolerance: 5%  Resistance: 820R  Power Rating: 500mW  Case Code (Imperial): 1210  [RES_1210]
R18  Resistance Tolerance: 1%  Resistance: 22R  Power Rating: 100mW  Case Code (Imperial): 0603  [RES_0603]  (hidden comment: 0603WAF220JT5E)
R19  Resistance Tolerance: 1%  Resistance: 100R  Power Rating: 100mW  Case Code (Imperial): 0603  [RES_0603]  (hidden comment: 0603WAF1000T5E)
R20  Resistance Tolerance: 1%  Resistance: 22R  Power Rating: 100mW  Case Code (Imperial): 0603  [RES_0603]  (hidden comment: 0603WAF220JT5E)
R21  Resistance Tolerance: 1%  Resistance: 22R  Power Rating: 100mW  Case Code (Imperial): 0603  [RES_0603]  (hidden comment: 0603WAF220JT5E)
R22  Resistance Tolerance: 1%  Resistance: 22R  Power Rating: 100mW  Case Code (Imperial): 0603  [RES_0603]  (hidden comment: 0603WAF220JT5E)
R23  Resistance Tolerance: 1%  Resistance: 22R  Power Rating: 100mW  Case Code (Imperial): 0603  [RES_0603]  (hidden comment: 0603WAF220JT5E)
R24  Resistance Tolerance: 1%  Resistance: 22R  Power Rating: 100mW  Case Code (Imperial): 0603  [RES_0603]  (hidden comment: 0603WAF220JT5E)
R25  Resistance Tolerance: 1%  Resistance: 22R  Power Rating: 100mW  Case Code (Imperial): 0603  [RES_0603]  (hidden comment: 0603WAF220JT5E)
R26  Resistance Tolerance: 1%  Resistance: 22R  Power Rating: 100mW  Case Code (Imperial): 0603  [RES_0603]  (hidden comment: 0603WAF220JT5E)
R27  Resistance Tolerance: 1%  Resistance: 22R  Power Rating: 100mW  Case Code (Imperial): 0603  [RES_0603]  (hidden comment: 0603WAF220JT5E)
R28  Resistance Tolerance: 1%  Resistance: 22R  Power Rating: 100mW  Case Code (Imperial): 0603  [RES_0603]  (hidden comment: 0603WAF220JT5E)
R29  Resistance Tolerance: 1%  Resistance: 22R  Power Rating: 100mW  Case Code (Imperial): 0603  [RES_0603]  (hidden comment: 0603WAF220JT5E)
R30  Resistance Tolerance: 1%  Resistance: 22R  Power Rating: 100mW  Case Code (Imperial): 0603  [RES_0603]  (hidden comment: 0603WAF220JT5E)
R31  Resistance Tolerance: 1%  Resistance: 22R  Power Rating: 100mW  Case Code (Imperial): 0603  [RES_0603]  (hidden comment: 0603WAF220JT5E)
R32  Resistance Tolerance: 1%  Resistance: 100R  Power Rating: 100mW  Case Code (Imperial): 0603  [RES_0603]  (hidden comment: 0603WAF1000T5E)
R33  Resistance Tolerance: 1%  Resistance: 22R  Power Rating: 100mW  Case Code (Imperial): 0603  [RES_0603]  (hidden comment: 0603WAF220JT5E)
R34  Resistance Tolerance: 1%  Resistance: 10k  Power Rating: 100mW  Case Code (Imperial): 0603  [RES_0603]  (hidden comment: 0603WAF1002T5E)
R35  Resistance Tolerance: 1%  Resistance: 22R  Power Rating: 100mW  Case Code (Imperial): 0603  [RES_0603]  (hidden comment: 0603WAF220JT5E)
R36  Resistance Tolerance: 1%  Resistance: 100R  Power Rating: 100mW  Case Code (Imperial): 0603  [RES_0603]  (hidden comment: 0603WAF1000T5E)
R37  Resistance Tolerance: 1%  Resistance: 100R  Power Rating: 100mW  Case Code (Imperial): 0603  [RES_0603]  (hidden comment: 0603WAF1000T5E)
R77  Resistance: 10k  Case Code (Imperial): 0603  [RES_0603]  (hidden comment: NCP18XH103F03RB)
R78  Resistance: 10k  Case Code (Imperial): 0603  [RES_0603]  (hidden comment: NCP18XH103F03RB)
R97  Resistance Tolerance: 1%  Resistance: 10k  Power Rating: 100mW  Case Code (Imperial): 0603  [RES_0603]  (hidden comment: 0603WAF1002T5E)
R98  Resistance Tolerance: 1%  Resistance: 100R  Power Rating: 100mW  Case Code (Imperial): 0603  [RES_0603]  (hidden comment: 0603WAF1000T5E)
R99  Resistance Tolerance: 1%  Resistance: 10k  Power Rating: 100mW  Case Code (Imperial): 0603  [RES_0603]  (hidden comment: 0603WAF1002T5E)
R100  Resistance Tolerance: 1%  Resistance: 100R  Power Rating: 100mW  Case Code (Imperial): 0603  [RES_0603]  (hidden comment: 0603WAF1000T5E)
R103  Resistance Tolerance: 1%  Resistance: 86k6  Power Rating: 100mW  Case Code (Imperial): 0603  [RES_0603]  (hidden comment: 0603WAF8662T5E)
R104  Resistance Tolerance: 1%  Resistance: 86k6  Power Rating: 100mW  Case Code (Imperial): 0603  [RES_0603]  (hidden comment: 0603WAF8662T5E)
R105  Resistance Tolerance: 1%  Resistance: 10k  Power Rating: 100mW  Case Code (Imperial): 0603  [RES_0603]  (hidden comment: 0603WAF1002T5E)
R106  Resistance Tolerance: 1%  Resistance: 100R  Power Rating: 100mW  Case Code (Imperial): 0603  [RES_0603]  (hidden comment: 0603WAF1000T5E)
R107  Resistance Tolerance: 1%  Resistance: 10k  Power Rating: 100mW  Case Code (Imperial): 0603  [RES_0603]  (hidden comment: 0603WAF1002T5E)
R108  Resistance Tolerance: 1%  Resistance: 10k  Power Rating: 100mW  Case Code (Imperial): 0603  [RES_0603]  (hidden comment: 0603WAF1002T5E)

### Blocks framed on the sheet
BQ7721606 override: Q7 Q8 R97-R100
Fuse control: Q9 R106 R107
External LDO: C12 C13 D13 Q4 R12 R13 R16 R17
Status LEDs: D41-D44 R103-R105 R108

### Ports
5V LDO (out, see BMS[3A]), ALRT (out, see BMS[3B], MCU[1C]), BAT+ (in, see BMS[2A], BAT+ to 5V1 STEP-DOWN[3B], BMS[1A], BQ34Z100 FUEL GAUGE[3A]), CFETOFF (in, see BMS[3C], MCU[1C]), COUT (in, see BMS[2A], BQ7721606[7B], MCU[1B]), DFETOFF (in, see BMS[3C], MCU[1C]), DOUT (in, see BMS[2A], BQ7721606[7B], MCU[1A]), FUSE (out, see BMS[2B], BMS[1B]), GND (in, see BMS[2C], 5V to 3V3 LDO[3B], BAT+ to 5V1 STEP-DOWN[3C], BQ34Z100 FUEL GAUGE[3C], MCU[1C]), PACK+ (out, see BMS[3A], BMS[8A]), RST/SHUT (in, see BMS[3B], MCU[1C]), SCL (bidir, see BMS[3C], BMS[8C], BQ34Z100 FUEL GAUGE[5B], MCU[1B]), SDA (bidir, see BMS[3C], BMS[8C], BQ34Z100 FUEL GAUGE[5B], MCU[1B]), SRN (in, see BMS[3C], BQ34Z100 FUEL GAUGE[4C]), SRP (in, see BMS[2C], BQ34Z100 FUEL GAUGE[4C]), TS2+ (in, see BMS[2C], BMS[1C], ESD battery side[5C]), TS2- (in, see BMS[2C], BMS[1C], ESD battery side[5C]), VC1 (in, see BMS[2B], BMS[1B], ESD battery side[5B]), VC2 (in, see BMS[2B], BMS[1B], ESD battery side[5B]), VC3 (in, see BMS[2B], BMS[1B], ESD battery side[5B]), VC4 (in, see BMS[2B], BMS[1B], ESD battery side[5B]), VC5 (in, see BMS[2B], BMS[1B], ESD battery side[5B]), VC6 (in, see BMS[2B], BMS[1B], ESD battery side[5B]), VC7 (in, see BMS[2B], BMS[1B], ESD battery side[5B]), VC8 (in, see BMS[2B], BMS[1B], ESD battery side[5B]), VC9 (in, see BMS[2B], BMS[1B], ESD battery side[5B]), VC10 (in, see BMS[2B], BMS[1B], ESD battery side[5B]), VC11 (in, see BMS[2B], BMS[1B], ESD battery side[5B]), VC12 (in, see BMS[2B], BMS[1B], ESD battery side[5B])

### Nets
GND_BMS: C9.1 C12.1 C13.1 C14.1 C15.1 C20.1 C24.1 C25.1 C26.1 C27.1 C29.2 C30.1 C53.1 C54.1 D11.A D12.A D14.A D15.A IC1.17(VSS) NT3.2 Q7.S Q8.S Q9.S R34.1 R35.1 R77.1 R78.1 R103.2 R104.2 R105.2 R107.1 R108.2 ; port GND
ALRT: R31.2 ; port ALRT
BAT: C7.1 C9.2 IC1.47(BAT) R19.2
BAT+: C3.1 D7.A D13.A D16.A Q1.S R2.1 R10.1 ; port BAT+  [also labelled C13]
BREG: IC1.37(BREG) Q4.B
C1: R33.1 ; port VC1
C2: R30.1 ; port VC2
C3: R28.1 ; port VC3
C4: R26.1 ; port VC4
C5: R25.1 ; port VC5
C6: R24.1 ; port VC6
C7: R23.1 ; port VC7
C8: R22.1 ; port VC8
C9: R21.1 ; port VC9
C10: R20.1 ; port VC10
C11: R18.1 ; port VC11
C12: R14.1 ; port VC12
CFETOFF: IC1.29(CFETOFF) ; port CFETOFF
CHG: IC1.45(CHG) R6.1
COUT: R100.1 ; port COUT
CP1: C7.2 IC1.46(CP1)
DFETOFF: IC1.30(DFETOFF) ; port DFETOFF
DOUT: R98.1 ; port DOUT
DSG: D11.K IC1.43(DSG) R7.1 R8.1
FUSE: D44.A IC1.38(FUSE) R106.2
G_CHG: D7.K D41.A Q1.G R2.2 R6.2 R99.2
G_DSG: D8.K D9.A D42.A Q2.G Q3.D R3.1 R4.2 R97.2
LD: D15.K IC1.41(LD) R15.1
NC44: IC1.44(NC)
PACK: D14.K IC1.42(PACK) R11.1
PACK+: C4.2 D8.A D10.A Q2.S Q3.S R3.2 R5.2 R11.2 R15.2 ; port PACK+
REG1: C15.2 D43.A IC1.35(REG1) ; port 5V LDO
REG2: C14.2 IC1.34(REG2)
REG18: C24.2 IC1.24(REG18)
REGIN: C12.2 IC1.36(REGIN) Q4.E
RST/SHUT: R32.2 ; port RST/SHUT
RST/SHUT BMS: C25.2 IC1.33(RST_SHUT) R32.1 R34.2
SCLt: R29.2 ; port SCL
SDAt: R27.2 ; port SDA
SRN: C28.2 C30.2 IC1.20(SRN) R37.2
SRP: C28.1 C29.1 IC1.18(SRP) R36.2
TS1: C20.2 IC1.21(TS1) ; port TS2+
TS2: C53.2 IC1.22(TS2/WAKE) R78.2
TS2- C: NT3.1 ; port TS2-
TS3: C54.2 IC1.23(TS3) R77.2
VC0: C27.2 IC1.16(VC0) R35.2
VC1: C23.1 C26.2 IC1.15(VC1) R33.2
VC2: C22.1 C23.2 IC1.14(VC2) R30.2
VC3: C21.1 C22.2 IC1.13(VC3) R28.2
VC4: C19.1 C21.2 IC1.12(VC4) R26.2
VC5: C18.1 C19.2 IC1.11(VC5) R25.2
VC6: C17.1 C18.2 IC1.10(VC6) R24.2
VC7: C16.1 C17.2 IC1.9(VC7) R23.2
VC8: C11.1 C16.2 IC1.8(VC8) R22.2
VC9: C10.1 C11.2 IC1.7(VC9) R21.2
VC10: C8.1 C10.2 IC1.6(VC10) R20.2
VC11: C6.1 C8.2 IC1.3(VC13) IC1.4(VC12) IC1.5(VC11) R18.2
VC12: C5.1 C6.2 IC1.1(VC15) IC1.2(VC14) R14.2
VC13: C5.2 IC1.48(VC16) R10.2
NetC3_2: C3.2 C4.1
NetC13_2: C13.2 Q4.C R16.1 R17.1
NetD9_K: D9.K R7.2
NetD10_K: D10.K Q3.G R5.1 R9.2
NetD12_K: D12.K R9.1
NetD13_K: D13.K R12.2 R13.2
NetD16_K: D16.K R19.1
NetD41_K: D41.K R103.1
NetD42_K: D42.K R104.1
NetD43_K: D43.K R105.1
NetD44_K: D44.K R108.1
NetF3_3: Q9.D ; port FUSE
NetIC1_25: IC1.25(ALERT) R31.1
NetIC1_26: IC1.26(SCL) R29.1
NetIC1_27: IC1.27(SDA) R27.1
NetNT1_2: R36.1 ; port SRP
NetNT2_2: R37.1 ; port SRN
NetQ1_D: Q1.D Q2.D
NetQ7_D: Q7.D R97.1
NetQ7_G: Q7.G R98.2
NetQ8_D: Q8.D R99.1
NetQ8_G: Q8.G R100.2
NetQ9_G: Q9.G R106.1 R107.2
NetR4_1: R4.1 R8.2
NetR12_1: R12.1 R13.1 R16.2 R17.2

Not connected (* = marked no-connect by the designer): IC1 19(NC)* 28(HDQ)* 31(DCHG)* 32(DDSG)* 39(PDSG)* 40(PCHG)*

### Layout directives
net class VC1: C1, VC1
net class VC2: C2, VC2
net class VC3: C3, VC3
net class VC4: C4, VC4
net class VC5: C5, VC5
net class VC6: C6, VC6
net class VC7: C7, VC7
net class VC8: C8, VC8
net class VC9: C9, VC9
net class VC10: C10, VC10
net class VC11: C11, VC11
net class VC12: C12, VC12
net class BAT+: BAT, BAT+, CHG, CP1, G_CHG, NC44, NetD13_K, NetD16_K, NetQ8_D, VC13
net class PACK+: DSG, G_DSG, LD, NetD9_K, NetD12_K, NetQ7_D, NetR4_1, PACK
net class BMS PP MID: NetQ1_D

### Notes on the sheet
- (near R11) Reverse charge protection.
- (near IC1) Configure to 5V.
- Place next to shunt
- Place next to power path fets.
- Test points

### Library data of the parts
C3 C4 = CC0603KRX7R0BB104: Cap 100nF 100V 0603 X7R; Manufacturer: YAGEO
C5 C6 C8 C10 C11 C16-C19 C21-C23 C26 C27 = CL10B224KA8NNNC: Cap 220nF 25V 0603 X7R; Manufacturer: Samsung
C7 = CL10B474KA8NNNC: Cap 470nF 25V 0603 X7R; Manufacturer: Samsung
C9 C13 = CC0805KKX7R0BB105: Cap 1uF 100V 0805 X7R; Manufacturer: Yageo
C12 = CL10B223KB8NNNC: Cap 22nF 50V 0603 X7R; Manufacturer: Samsung
C14 C15 C24 = CL10A106MA8NRNC: Cap 10uF 25V 0603 X5R; Manufacturer: Samsung
C20 C53 C54 = 0603B222K500NT: Cap 2n2F 50V 0603 X7R; Manufacturer: FH
C25 C28-C30 = CC0603KRX7R9BB104: Cap 100nF 50V 0603 X7R; Manufacturer: Yageo
D7 D8 D10 = BZT52C16: Zener 16V 500mW SOD-123; Manufacturer: TWGMC
D9 D11-D16 = SS210F: Schottky 100V 2A 850mVf SMAF; Manufacturer: GOODWORK
D41-D43 = PSC-1608U52GC-G4: LED Green 0603 20mA; Manufacturer: HONGLITRONIC
D44 = XL-1608SURC-06: LED Red 0603 25mA; Manufacturer: Xinglight
IC1 = BQ76952PFBR: BMS IC 3~16s; Manufacturer: Texas Instruments
NT3 = NetTie: Net Tie
Q1 Q2 = HYG053N10NS1C2: Nmos 100V 95A 5.3mR PDFN5x6-8L; Manufacturer: HUAYI
Q3 = 2N7002: nMOS 60V 115mA SOT-23; Manufacturer: Jiangsu Changjing Electronics Technology Co., Ltd.
Q4 = CZT5551: NPN 160V 600mA SOT-223 1W; Manufacturer: Jiangsu
Q7 Q8 = BSS123: Nmos 100V 170mA SOT-23; Manufacturer: hongjiacheng
Q9 = 5N10-MS: Nmos 100V 5A SOT-23; Manufacturer: MSKSEMI
R2 R3 R5 = 0603WAF1005T5E: Res 10M 0603 1% 100mW 75V; Manufacturer: Uni-Royal
R4 R8 = HP06W2J0512T5E: Res 5k1 1206 5% 500mW 200V; Manufacturer: Uni-Royal
R6 R34 R97 R99 R105 R107 R108 = 0603WAF1002T5E: Res 10k 0603 1% 100mW 75V; Manufacturer: Uni-Royal
R7 = 0603WAF5101T5E: Res 5k1 0603 1% 100mW 75V; Manufacturer: Uni-Royal
R9 R11 R15 = 1206W4F1002T5E: Res 10k 1206 1% 250mW 200V; Manufacturer: Uni-Royal
R10 R14 R18 R20-R31 R33 R35 = 0603WAF220JT5E: Res 22R 0603 1% 100mW 75V; Manufacturer: Uni-Royal
R12 R13 R16 R17 = FRC1210J821 TS: Res 820R 1210 5% 500mW 200V; Manufacturer: FOJAN
R19 R32 R36 R37 R98 R100 R106 = 0603WAF1000T5E: Res 100R 0603 1% 100mW 75V; Manufacturer: Uni-Royal
R77 R78 = NCP18XH103F03RB: NTC 10k 0603 1% 3455K; Manufacturer: Murata
R103 R104 = 0603WAF8662T5E: Res 86k6 0603 1% 100mW 75V; Manufacturer: Uni-Royal

## Sheet BQ34Z100 FUEL GAUGE.SchDoc
size A3; SheetNumber: 7; SheetTotal: 10
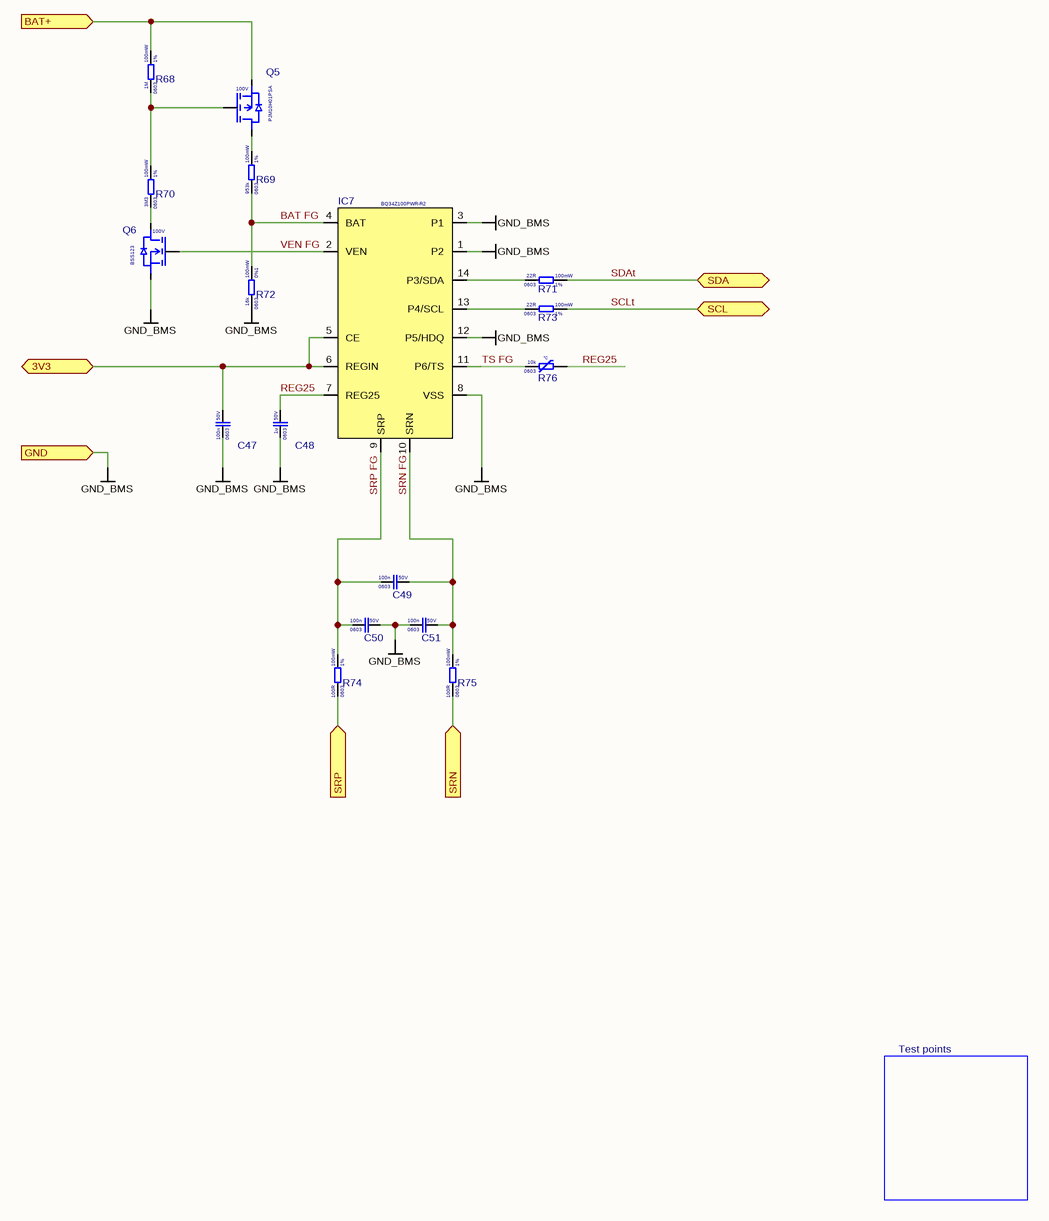
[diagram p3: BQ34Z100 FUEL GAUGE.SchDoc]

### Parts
C47  Voltage Rating: 50V  Case Code (Imperial): 0603  Capacitance: 100n  [CAP 0603]  (hidden comment: CC0603KRX7R9BB104)
C48  Voltage Rating: 50V  Case Code (Imperial): 0603  Capacitance: 1u  [CAP 0603]  (hidden comment: CL10A105KB8NNNC)
C49  Voltage Rating: 50V  Case Code (Imperial): 0603  Capacitance: 100n  [CAP 0603]  (hidden comment: CC0603KRX7R9BB104)
C50  Voltage Rating: 50V  Case Code (Imperial): 0603  Capacitance: 100n  [CAP 0603]  (hidden comment: CC0603KRX7R9BB104)
C51  Voltage Rating: 50V  Case Code (Imperial): 0603  Capacitance: 100n  [CAP 0603]  (hidden comment: CC0603KRX7R9BB104)
IC7  BQ34Z100PWR-R2  [TSSOP-14]
Q5  Voltage: 100V  [SOT-23 GSD]  (hidden comment: PJM10H01PSA)
Q6  Voltage: 100V  [SOT-23 GSD]  (hidden comment: BSS123)
R68  Resistance Tolerance: 1%  Resistance: 1M  Power Rating: 100mW  Case Code (Imperial): 0603  [RES_0603]  (hidden comment: 0603WAF1004T5E)
R69  Resistance Tolerance: 1%  Resistance: 953k  Power Rating: 100mW  Case Code (Imperial): 0603  [RES_0603]  (hidden comment: AC0603FR-07953KL)
R70  Resistance Tolerance: 1%  Resistance: 3M3  Power Rating: 100mW  Case Code (Imperial): 0603  [RES_0603]  (hidden comment: 0603WAF3304T5E)
R71  Resistance Tolerance: 1%  Resistance: 22R  Power Rating: 100mW  Case Code (Imperial): 0603  [RES_0603]  (hidden comment: 0603WAF220JT5E)
R72  Resistance Tolerance: 0%1  Resistance: 16k  Power Rating: 100mW  Case Code (Imperial): 0603  [RES_0603]  (hidden comment: RT0603BRD0716KL)
R73  Resistance Tolerance: 1%  Resistance: 22R  Power Rating: 100mW  Case Code (Imperial): 0603  [RES_0603]  (hidden comment: 0603WAF220JT5E)
R74  Resistance Tolerance: 1%  Resistance: 100R  Power Rating: 100mW  Case Code (Imperial): 0603  [RES_0603]  (hidden comment: 0603WAF1000T5E)
R75  Resistance Tolerance: 1%  Resistance: 100R  Power Rating: 100mW  Case Code (Imperial): 0603  [RES_0603]  (hidden comment: 0603WAF1000T5E)
R76  Resistance: 10k  Case Code (Imperial): 0603  [RES_0603]  (hidden comment: NCP18XH103F03RB)

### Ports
3V3 (bidir, see BMS[4C], 5V to 3V3 LDO[5B]), BAT+ (in, see BMS[4D], BAT+ to 5V1 STEP-DOWN[3B], BMS[1A], BQ76952 BMS[1A]), GND (in, see BMS[4D], 5V to 3V3 LDO[3B], BAT+ to 5V1 STEP-DOWN[3C], BQ76952 BMS[1D], MCU[1C]), SCL (bidir, see BMS[4C], BMS[8C], BQ76952 BMS[7C], MCU[1B]), SDA (bidir, see BMS[4C], BMS[8C], BQ76952 BMS[7C], MCU[1B]), SRN (in, see BMS[4D], BQ76952 BMS[5D]), SRP (in, see BMS[4D], BQ76952 BMS[5D])

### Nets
GND_BMS: C47.1 C48.1 C50.2 C51.1 IC7.1(P2) IC7.3(P1) IC7.8(VSS) IC7.12(P5/HDQ) Q6.S R72.1 ; port GND
VDD: C47.2 IC7.5(CE) IC7.6(REGIN) ; port 3V3
BAT FG: IC7.4(BAT) R69.1 R72.2
BAT+: Q5.S R68.2 ; port BAT+
REG25: C48.2 IC7.7(REG25) R76.2
SCLt: R73.2 ; port SCL
SDAt: R71.2 ; port SDA
SRN FG: C49.2 C51.2 IC7.10(SRN) R75.2
SRP FG: C49.1 C50.1 IC7.9(SRP) R74.2
TS FG: IC7.11(P6/TS) R76.1
VEN FG: IC7.2(VEN) Q6.G
NetIC7_13: IC7.13(P4/SCL) R73.1
NetIC7_14: IC7.14(P3/SDA) R71.1
NetNT1_2: R74.1 ; port SRP
NetNT2_2: R75.1 ; port SRN
NetQ5_D: Q5.D R69.2
NetQ5_G: Q5.G R68.1 R70.2
NetQ6_D: Q6.D R70.1

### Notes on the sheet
- Test points

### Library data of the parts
C47 C49-C51 = CC0603KRX7R9BB104: as C25 on sheet BQ76952 BMS
C48 = CL10A105KB8NNNC: Cap 1uF 50V 0603 X5R; Manufacturer: Samsung
IC7 = BQ34Z100PWR-R2: Fuel gauge; Manufacturer: Texas Instruments
Q5 = PJM10H01PSA: Pmos 100V 1A 650mR SOT-23; Manufacturer: PJSEMI
Q6 = BSS123: as Q7 on sheet BQ76952 BMS
R68 = 0603WAF1004T5E: Res 1M 0603 1% 100mW 75V; Manufacturer: Uni-Royal
R69 = AC0603FR-07953KL: Res 953k 0603 1% 100mW 75V; Manufacturer: YAGEO
R70 = 0603WAF3304T5E: Res 3M3 0603 1% 100mW 75V; Manufacturer: Uni-Royal
R71 R73 = 0603WAF220JT5E: as R10 on sheet BQ76952 BMS
R72 = RT0603BRD0716KL: Res 16k 0603 0.1% 100mW 75V 25ppm; Manufacturer: YAGEO
R74 R75 = 0603WAF1000T5E: as R19 on sheet BQ76952 BMS
R76 = NCP18XH103F03RB: as R77 on sheet BQ76952 BMS

## Sheet MCU.SchDoc
size A3; SheetNumber: 4; SheetTotal: 10
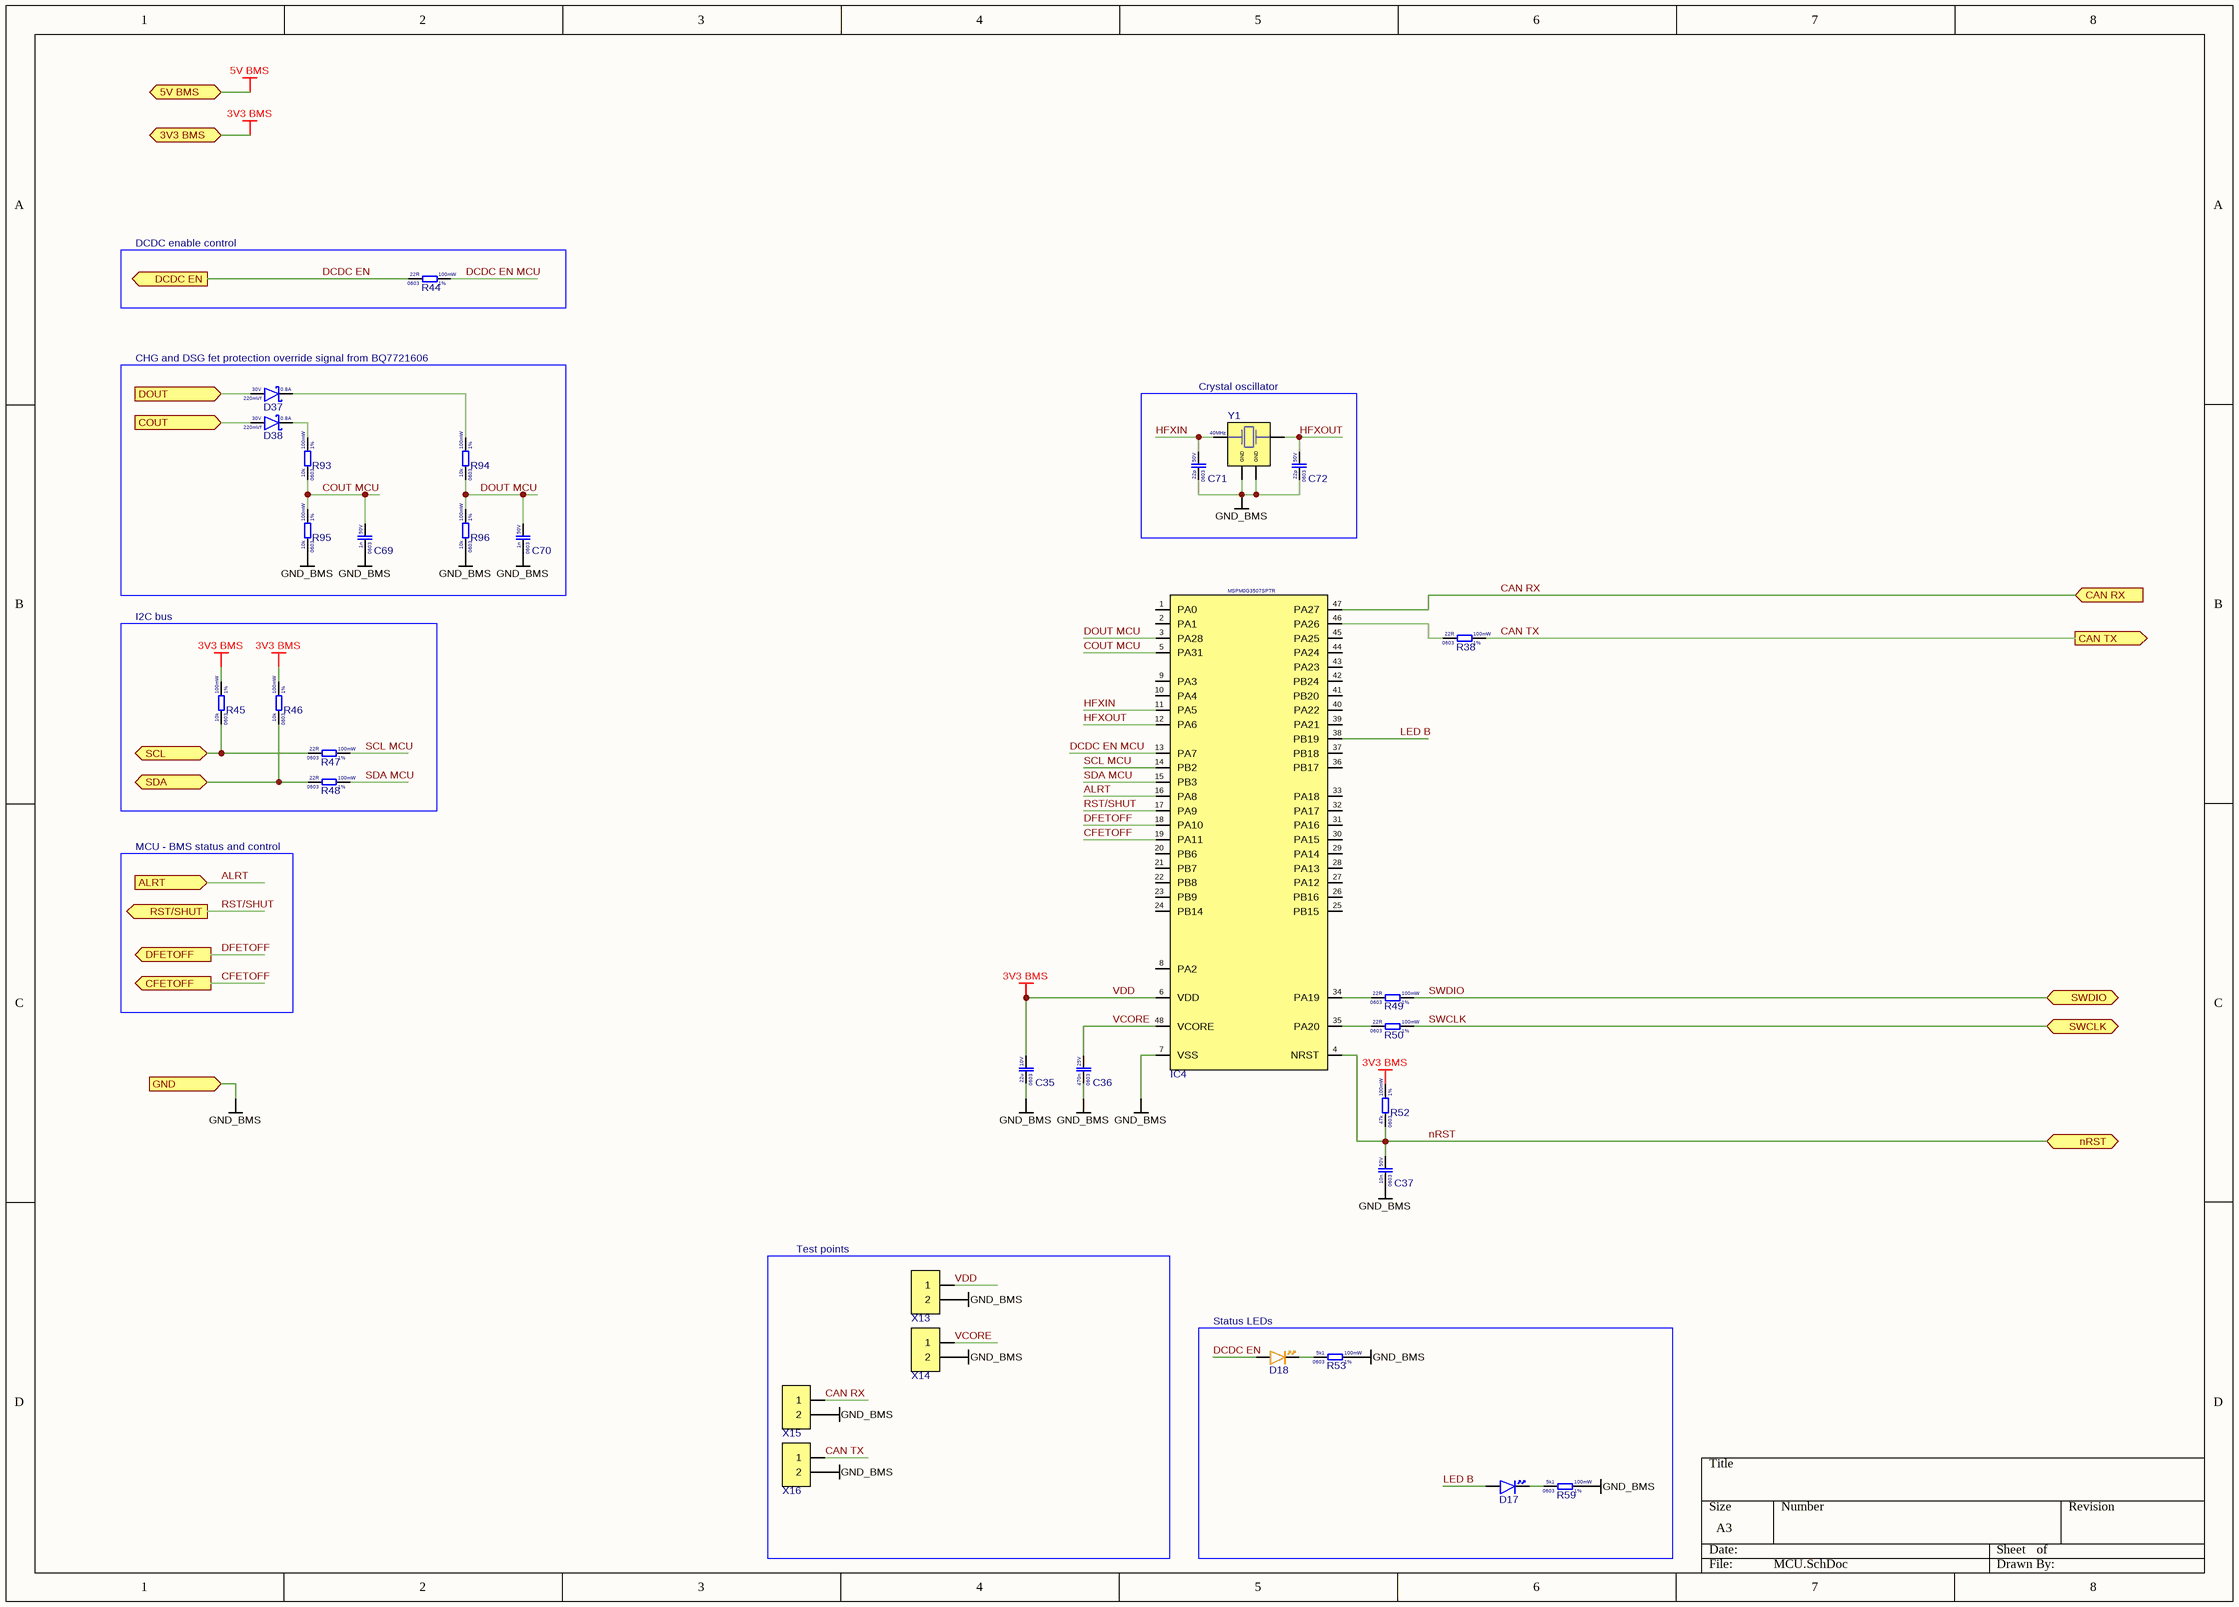
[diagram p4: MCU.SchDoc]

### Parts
C35  Voltage Rating: 10V  Case Code (Imperial): 0603  Capacitance: 22u  [CAP 0603]  (hidden comment: CGA0603X5R226M100JT)
C36  Voltage Rating: 25V  Case Code (Imperial): 0603  Capacitance: 470n  [CAP 0603]  (hidden comment: CL10B474KA8NNNC)
C37  Voltage Rating: 50V  Case Code (Imperial): 0603  Capacitance: 10n  [CAP 0603]  (hidden comment: 0603B103K500NT)
C69  Voltage Rating: 50V  Case Code (Imperial): 0603  Capacitance: 1n  [CAP 0603]  (hidden comment: CL10B102KB8NNNC)
C70  Voltage Rating: 50V  Case Code (Imperial): 0603  Capacitance: 1n  [CAP 0603]  (hidden comment: CL10B102KB8NNNC)
C71  Voltage Rating: 50V  Case Code (Imperial): 0603  Capacitance: 22p  [CAP 0603]  (hidden comment: CL10C220JB8NNNC)
C72  Voltage Rating: 50V  Case Code (Imperial): 0603  Capacitance: 22p  [CAP 0603]  (hidden comment: CL10C220JB8NNNC)
D17  XL-1608UBC-04  [DIODE_0603_BLUE]  (value not drawn)
D18  XL-1608UOC-06  [DIODE_0603_ORANGE]  (value not drawn)
D37  Forward Voltage: 220mVf  Forward Current: 0.8A  Reverse Voltage: 30V  [SOD-323]  (hidden comment: CUS08F30,H3F)
D38  Forward Voltage: 220mVf  Forward Current: 0.8A  Reverse Voltage: 30V  [SOD-323]  (hidden comment: CUS08F30,H3F)
IC4  MSPM0G3507SPTR  [LQFP-48]
R38  Resistance Tolerance: 1%  Resistance: 22R  Power Rating: 100mW  Case Code (Imperial): 0603  [RES_0603]  (hidden comment: 0603WAF220JT5E)
R44  Resistance Tolerance: 1%  Resistance: 22R  Power Rating: 100mW  Case Code (Imperial): 0603  [RES_0603]  (hidden comment: 0603WAF220JT5E)
R45  Resistance Tolerance: 1%  Resistance: 10k  Power Rating: 100mW  Case Code (Imperial): 0603  [RES_0603]  (hidden comment: 0603WAF1002T5E)
R46  Resistance Tolerance: 1%  Resistance: 10k  Power Rating: 100mW  Case Code (Imperial): 0603  [RES_0603]  (hidden comment: 0603WAF1002T5E)
R47  Resistance Tolerance: 1%  Resistance: 22R  Power Rating: 100mW  Case Code (Imperial): 0603  [RES_0603]  (hidden comment: 0603WAF220JT5E)
R48  Resistance Tolerance: 1%  Resistance: 22R  Power Rating: 100mW  Case Code (Imperial): 0603  [RES_0603]  (hidden comment: 0603WAF220JT5E)
R49  Resistance Tolerance: 1%  Resistance: 22R  Power Rating: 100mW  Case Code (Imperial): 0603  [RES_0603]  (hidden comment: 0603WAF220JT5E)
R50  Resistance Tolerance: 1%  Resistance: 22R  Power Rating: 100mW  Case Code (Imperial): 0603  [RES_0603]  (hidden comment: 0603WAF220JT5E)
R52  Resistance Tolerance: 1%  Resistance: 47k  Power Rating: 100mW  Case Code (Imperial): 0603  [RES_0603]  (hidden comment: 0603WAF4702T5E)
R53  Resistance Tolerance: 1%  Resistance: 5k1  Power Rating: 100mW  Case Code (Imperial): 0603  [RES_0603]  (hidden comment: 0603WAF5101T5E)
R59  Resistance Tolerance: 1%  Resistance: 5k1  Power Rating: 100mW  Case Code (Imperial): 0603  [RES_0603]  (hidden comment: 0603WAF5101T5E)
R93  Resistance Tolerance: 1%  Resistance: 10k  Power Rating: 100mW  Case Code (Imperial): 0603  [RES_0603]  (hidden comment: 0603WAF1002T5E)
R94  Resistance Tolerance: 1%  Resistance: 10k  Power Rating: 100mW  Case Code (Imperial): 0603  [RES_0603]  (hidden comment: 0603WAF1002T5E)
R95  Resistance Tolerance: 1%  Resistance: 10k  Power Rating: 100mW  Case Code (Imperial): 0603  [RES_0603]  (hidden comment: 0603WAF1002T5E)
R96  Resistance Tolerance: 1%  Resistance: 10k  Power Rating: 100mW  Case Code (Imperial): 0603  [RES_0603]  (hidden comment: 0603WAF1002T5E)
X13  HX PM1.27-1x2P ZC  [HX PM1.27-1x2P ZC]  (value not drawn)
X14  HX PM1.27-1x2P ZC  [HX PM1.27-1x2P ZC]  (value not drawn)
X15  HX PM1.27-1x2P ZC  [HX PM1.27-1x2P ZC]  (value not drawn)
X16  HX PM1.27-1x2P ZC  [HX PM1.27-1x2P ZC]  (value not drawn)
Y1  Frequency: 40MHz  [S3240000121040]  (hidden comment: S3240000121040)

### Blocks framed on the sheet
DCDC enable control: R44
CHG and DSG fet protection override signal from BQ7721606: C69 C70 D37 D38 R93-R96
Crystal oscillator: C71 C72 Y1
I2C bus: R45-R48
Test points: X13-X16
Status LEDs: D17 D18 R53 R59

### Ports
3V3 BMS (bidir, see BMS[4B]), 5V BMS (bidir, see BMS[4B]), ALRT (in, see BMS[4B], BQ76952 BMS[7C]), CAN RX (in, see BMS[4B], BMS[8B]), CAN TX (out, see BMS[4B], BMS[8B]), CFETOFF (out, see BMS[4C], BQ76952 BMS[7C]), COUT (in, see BMS[4B], BQ76952 BMS[3A], BQ7721606[7B]), DCDC EN (out, see BMS[4B]), DFETOFF (out, see BMS[4C], BQ76952 BMS[7C]), DOUT (in, see BMS[4B], BQ76952 BMS[3A], BQ7721606[7B]), GND (in, see BMS[4C], 5V to 3V3 LDO[3B], BAT+ to 5V1 STEP-DOWN[3C], BQ34Z100 FUEL GAUGE[3C], BQ76952 BMS[1D]), nRST (bidir, see BMS[4B], BMS[8B]), RST/SHUT (out, see BMS[4B], BQ76952 BMS[7C]), SCL (bidir, see BMS[4C], BMS[8C], BQ34Z100 FUEL GAUGE[5B], BQ76952 BMS[7C]), SDA (bidir, see BMS[4C], BMS[8C], BQ34Z100 FUEL GAUGE[5B], BQ76952 BMS[7C]), SWCLK (bidir, see BMS[4B], BMS[8B]), SWDIO (bidir, see BMS[4B], BMS[8B])

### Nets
GND_BMS: C35.1 C36.1 C37.1 C69.1 C70.1 C71.1 C72.1 IC4.7(VSS) R53.2 R59.2 R95.1 R96.1 X13.2 X14.2 X15.2 X16.2 Y1.2(GND) Y1.4(GND) ; port GND
VDD: C35.2 IC4.6(VDD) R45.2 R46.2 R52.2 X13.1 ; port 3V3 BMS  [also labelled 3V3 BMS]
ALRT: IC4.16(PA8) ; port ALRT
CAN RX: IC4.47(PA27) X15.1 ; port CAN RX
CAN TX: R38.2 X16.1 ; port CAN TX
CFETOFF: IC4.19(PA11) ; port CFETOFF
COUT: D38.A ; port COUT
COUT MCU: C69.2 IC4.5(PA31) R93.1 R95.2
DCDC EN: D18.A R44.1 ; port DCDC EN
DCDC EN MCU: IC4.13(PA7) R44.2
DFETOFF: IC4.18(PA10) ; port DFETOFF
DOUT: D37.A ; port DOUT
DOUT MCU: C70.2 IC4.3(PA28) R94.1 R96.2
HFXIN: C71.2 IC4.11(PA5) Y1.1
HFXOUT: C72.2 IC4.12(PA6) Y1.3
LED B: D17.A IC4.38(PB19)
nRST: C37.2 IC4.4(NRST) R52.1 ; port nRST
RST/SHUT: IC4.17(PA9) ; port RST/SHUT
SCL MCU: IC4.14(PB2) R47.2
SCLt: R45.1 R47.1 ; port SCL
SDA MCU: IC4.15(PB3) R48.2
SDAt: R46.1 R48.1 ; port SDA
SWCLK: R50.2 ; port SWCLK
SWDIO: R49.2 ; port SWDIO
VCORE: C36.2 IC4.48(VCORE) X14.1
NetD17_K: D17.K R59.1
NetD18_K: D18.K R53.1
NetD37_K: D37.K R94.2
NetD38_K: D38.K R93.2
NetIC4_34: IC4.34(PA19) R49.1
NetIC4_35: IC4.35(PA20) R50.1
NetIC4_46: IC4.46(PA26) R38.1

Not connected (* = marked no-connect by the designer): IC4 1(PA0) 2(PA1) 8(PA2) 9(PA3) 10(PA4) 20(PB6) 21(PB7) 22(PB8) 23(PB9) 24(PB14) 25(PB15) 26(PB16) 27(PA12) 28(PA13) 29(PA14) 30(PA15) 31(PA16) 32(PA17) 33(PA18) 36(PB17) 37(PB18) 39(PA21) 40(PA22) 41(PB20) 42(PB24) 43(PA23) 44(PA24) 45(PA25)

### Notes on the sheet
- MCU - BMS status and control

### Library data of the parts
C35 = CGA0603X5R226M100JT: Cap 22uF 10V 0603 X5R; Manufacturer: HRE
C36 = CL10B474KA8NNNC: as C7 on sheet BQ76952 BMS
C37 = 0603B103K500NT: Cap 10nF 50V 0603 X7R; Manufacturer: FH
C69 C70 = CL10B102KB8NNNC: as C1 on sheet BMS Arhitecture
C71 C72 = CL10C220JB8NNNC: Cap 22pF 50V 0603 C0G; Manufacturer: Samsung
D17 = XL-1608UBC-04: LED Blue 0603 25mA; Manufacturer: Xinglight
D18 = XL-1608UOC-06: LED Orange 0603 20mA; Manufacturer: XINGLIGHT
D37 D38 = CUS08F30,H3F: Schottky 30V 800mA 220mVf SOD-323; Manufacturer: Toshiba
IC4 = MSPM0G3507SPTR: MCU MSPM0G3507SPTR LQFP-48; Manufacturer: Texas Instruments
R38 R44 R47-R50 = 0603WAF220JT5E: as R10 on sheet BQ76952 BMS
R45 R46 R93-R96 = 0603WAF1002T5E: as R6 on sheet BQ76952 BMS
R52 = 0603WAF4702T5E: Res 47k 0603 1% 100mW 75V; Manufacturer: Uni-Royal
R53 R59 = 0603WAF5101T5E: as R7 on sheet BQ76952 BMS
X13-X16 = HX PM1.27-1x2P ZC: Female header 1x2 1.27mm THT Vertical; Manufacturer: hanxia
Y1 = S3240000121040: Crystal oscillator 40MHz SMD 12pF 40R 10ppm; Manufacturer: JGHC

## Sheet BAT+ to 5V1 STEP-DOWN.SchDoc
size A3; SheetNumber: 5; SheetTotal: 10
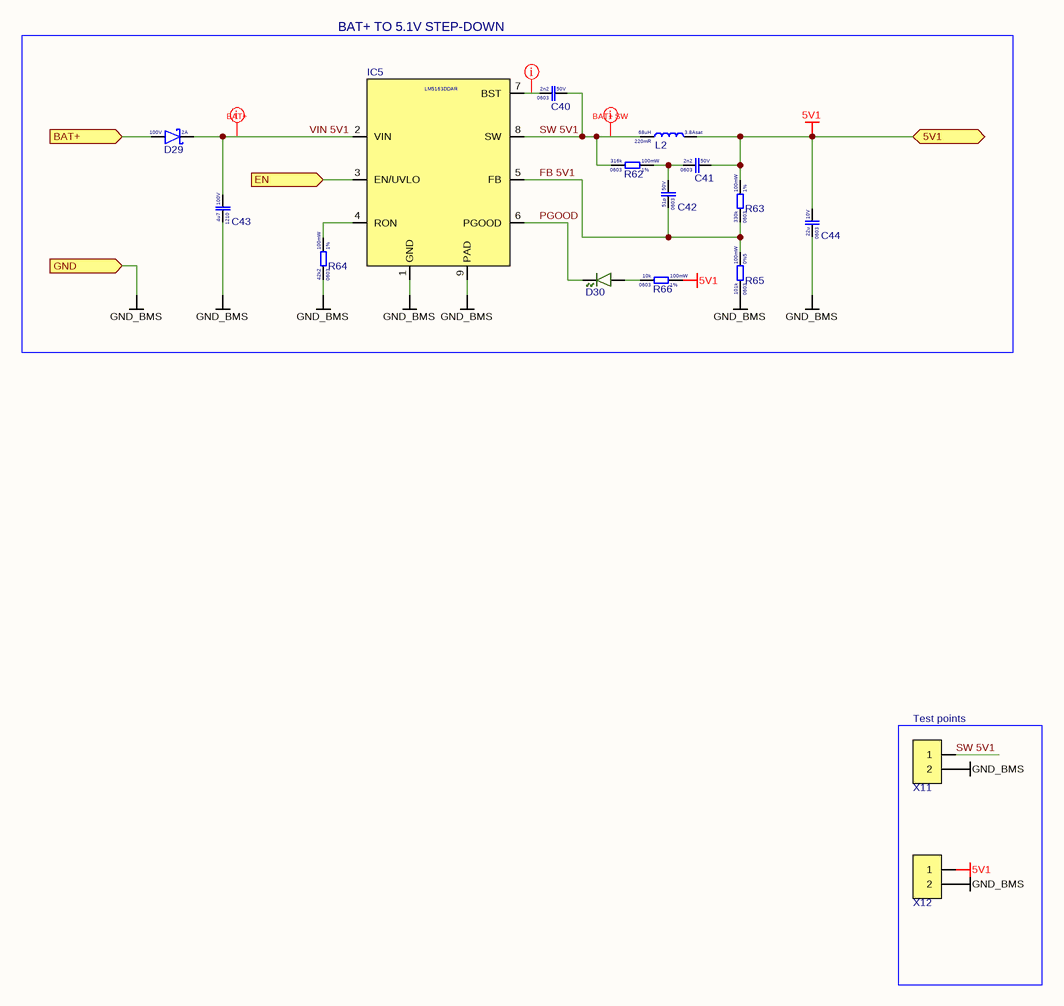
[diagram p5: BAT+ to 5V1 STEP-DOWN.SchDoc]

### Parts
C40  Voltage Rating: 50V  Case Code (Imperial): 0603  Capacitance: 2n2  [CAP 0603]  (hidden comment: 0603B222K500NT)
C41  Voltage Rating: 50V  Case Code (Imperial): 0603  Capacitance: 2n2  [CAP 0603]  (hidden comment: 0603B222K500NT)
C42  Voltage Rating: 50V  Case Code (Imperial): 0603  Capacitance: 51p  [CAP 0603]  (hidden comment: CC0603JRNPO9BN510)
C43  Voltage Rating: 100V  Case Code (Imperial): 1210  Capacitance: 4u7  [CAP_1210]  (hidden comment: HMK325C7475KN-TE)
C44  Voltage Rating: 10V  Case Code (Imperial): 0603  Capacitance: 22u  [CAP 0603]  (hidden comment: CGA0603X5R226M100JT)
D29  Forward Current: 2A  Reverse Voltage: 100V  [SMAF]  (hidden comment: SS210F)
D30  PSC-1608U52GC-G4  [DIODE_0603_GREEN]  (value not drawn)
IC5  LM5163DDAR  [ESOP-8]
L2  Resistance: 220mR  Saturation current: 3.8Asat  Inductance: 68uH  [IND 11.5x10mm]  (hidden comment: SMMS1040-680MT)
R62  Resistance Tolerance: 1%  Resistance: 316k  Power Rating: 100mW  Case Code (Imperial): 0603  [RES_0603]  (hidden comment: 0603WAF3163T5E)
R63  Resistance Tolerance: 1%  Resistance: 330k  Power Rating: 100mW  Case Code (Imperial): 0603  [RES_0603]  (hidden comment: 0603WAF3303T5E)
R64  Resistance Tolerance: 1%  Resistance: 42k2  Power Rating: 100mW  Case Code (Imperial): 0603  [RES_0603]  (hidden comment: 0603WAF4222T5E)
R65  Resistance Tolerance: 0%5  Resistance: 101k  Power Rating: 100mW  Case Code (Imperial): 0603  [RES_0603]  (hidden comment: RT0603DRE07101KL)
R66  Resistance Tolerance: 1%  Resistance: 10k  Power Rating: 100mW  Case Code (Imperial): 0603  [RES_0603]  (hidden comment: 0603WAF1002T5E)
X11  HX PM1.27-1x2P ZC  [HX PM1.27-1x2P ZC]  (value not drawn)
X12  HX PM1.27-1x2P ZC  [HX PM1.27-1x2P ZC]  (value not drawn)

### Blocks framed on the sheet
BAT+ TO 5.1V STEP-DOWN: C40-C44 D29 D30 IC5 L2 R62-R66
Test points: X11 X12

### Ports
5V1 (bidir, see BMS[4B]), BAT+ (in, see BMS[4B], BMS[1A], BQ34Z100 FUEL GAUGE[3A], BQ76952 BMS[1A]), EN (in, see BMS[4B]), GND (in, see BMS[4B], 5V to 3V3 LDO[3B], BQ34Z100 FUEL GAUGE[3C], BQ76952 BMS[1D], MCU[1C])

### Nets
5V1: C41.2 C44.2 L2.2 R63.2 R66.2 X12.1 ; port 5V1  [project net 5V BMS]
GND_BMS: C43.1 C44.1 IC5.1(GND) IC5.9(PAD) R64.1 R65.1 X11.2 X12.2 ; port GND
BAT+: D29.A ; port BAT+
DCDC EN: IC5.3(EN/UVLO) ; port EN
FB 5V1: C42.1 IC5.5(FB) R63.1 R65.2
PGOOD: D30.K IC5.6(PGOOD)
SW 5V1: C40.2 IC5.8(SW) L2.1 R62.1 X11.1
VIN 5V1: C43.2 D29.K IC5.2(VIN)
NetC40_1: C40.1 IC5.7(BST)
NetC41_1: C41.1 C42.2 R62.2
NetD30_A: D30.A R66.1
NetIC5_4: IC5.4(RON) R64.2

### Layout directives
net class BAT+: VIN 5V1
net class BAT+ SW: NetC40_1, SW 5V1

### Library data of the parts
C40 C41 = 0603B222K500NT: Cap 2n2F 50V 0603 X7R; Manufacturer: FH
C42 = CC0603JRNPO9BN510: Cap 51pF 50V 0603 NP0; Manufacturer: Yageo
C43 = HMK325C7475KN-TE: Cap 4.7uF 100V 1210 X7R; Manufacturer: Taiyo Yuden
C44 = CGA0603X5R226M100JT: Cap 22uF 10V 0603 X5R; Manufacturer: HRE
D29 = SS210F: as D9 on sheet BQ76952 BMS
D30 = PSC-1608U52GC-G4: as D41 on sheet BQ76952 BMS
IC5 = LM5163DDAR: DCDC Step-down Converter 9~100Vin 0.5Aout; Manufacturer: Texas Instruments
L2 = SMMS1040-680MT: Inductor 68uH 3.8A 220mR SMD 11.5x10mm; Manufacturer: SXN
R62 = 0603WAF3163T5E: Res 316k 0603 1% 100mW 75V; Manufacturer: Uni-Royal
R63 = 0603WAF3303T5E: Res 330k 0603 1% 100mW 75V; Manufacturer: Uni-Royal
R64 = 0603WAF4222T5E: Res 42k2 0603 1% 100mW 75V; Manufacturer: Uni-Royal
R65 = RT0603DRE07101KL: Res 101k 0603 0.5% 100mW 75V; Manufacturer: YAGEO
R66 = 0603WAF1002T5E: as R6 on sheet BQ76952 BMS
X11 X12 = HX PM1.27-1x2P ZC: as X13 on sheet MCU

## Sheet 5V to 3V3 LDO.SchDoc
size A3; SheetNumber: 6; SheetTotal: 10
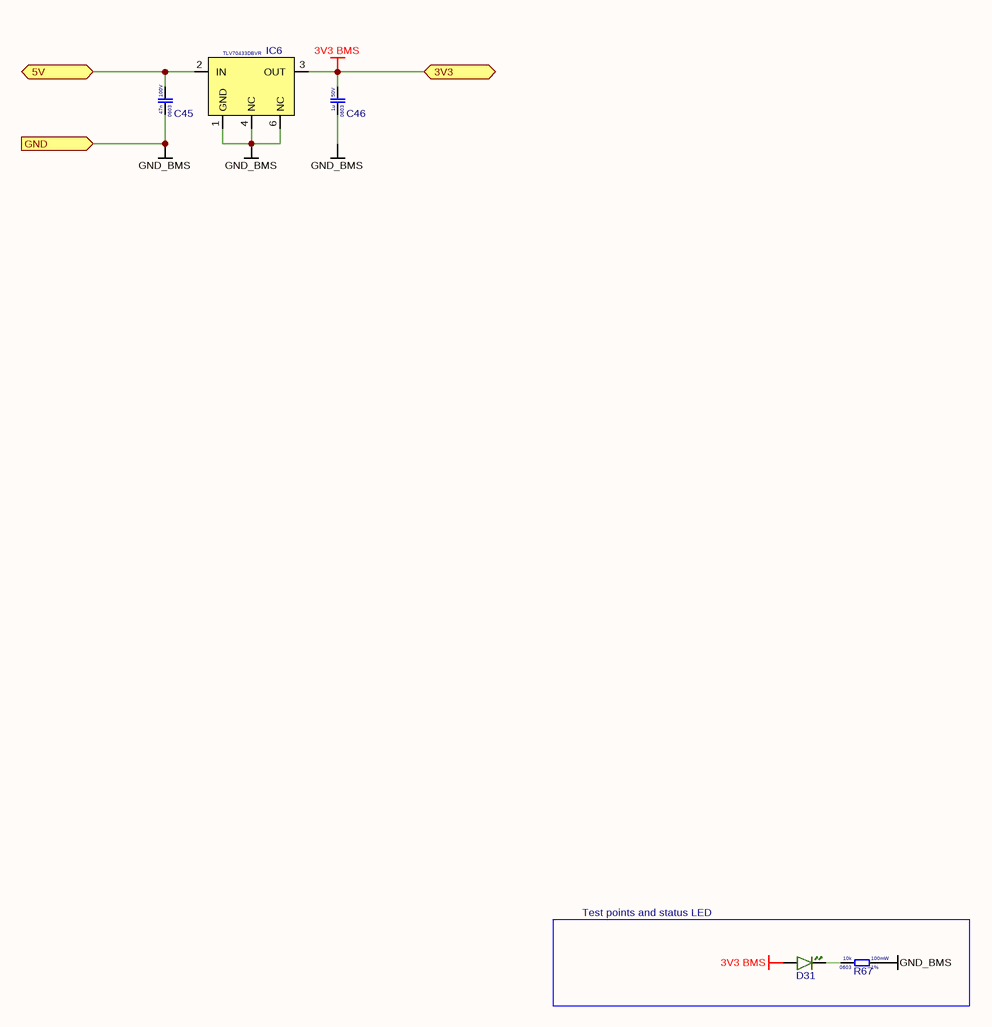
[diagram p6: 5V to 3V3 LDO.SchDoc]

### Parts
C45  Voltage Rating: 100V  Case Code (Imperial): 0603  Capacitance: 47n  [CAP 0603]  (hidden comment: CC0603KRX7R0BB473)
C46  Voltage Rating: 50V  Case Code (Imperial): 0603  Capacitance: 1u  [CAP 0603]  (hidden comment: CL10A105KB8NNNC)
D31  PSC-1608U52GC-G4  [DIODE_0603_GREEN]  (value not drawn)
IC6  TLV70433DBVR  [SOT-23-5]
R67  Resistance Tolerance: 1%  Resistance: 10k  Power Rating: 100mW  Case Code (Imperial): 0603  [RES_0603]  (hidden comment: 0603WAF1002T5E)

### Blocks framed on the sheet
Test points and status LED: D31 R67

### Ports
3V3 (bidir, see BMS[6B], BQ34Z100 FUEL GAUGE[3B]), 5V (bidir, see BMS[5B]), GND (in, see BMS[5B], BAT+ to 5V1 STEP-DOWN[3C], BQ34Z100 FUEL GAUGE[3C], BQ76952 BMS[1D], MCU[1C])

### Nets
3V3 BMS: C46.2 D31.A IC6.3(OUT) ; port 3V3  [project net VDD]
5V BMS: C45.2 IC6.2(IN) ; port 5V
GND_BMS: C45.1 C46.1 IC6.1(GND) IC6.4(NC) IC6.6(NC) R67.2 ; port GND
NetD31_K: D31.K R67.1

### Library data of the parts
C45 = CC0603KRX7R0BB473: Cap 47nF 100V 0603 X7R; Manufacturer: Yageo
C46 = CL10A105KB8NNNC: as C48 on sheet BQ34Z100 FUEL GAUGE
D31 = PSC-1608U52GC-G4: as D41 on sheet BQ76952 BMS
IC6 = TLV70433DBVR: LDO 24Vin 3.3Vout 150mA SOT-23-5; Manufacturer: Texas Instruments
R67 = 0603WAF1002T5E: as R6 on sheet BQ76952 BMS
